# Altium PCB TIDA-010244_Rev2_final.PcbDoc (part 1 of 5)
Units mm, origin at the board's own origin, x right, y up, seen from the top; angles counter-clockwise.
Board outline 155.23 x 187.6 mm, 4 copper layers (GND/Signal 1, Solid GND Layer 1, Solid Power Layer 1, GND/Signal Layer 2), stack 1.59 mm thick; 350 components, 237 nets, 1153 pads, 380 vias.
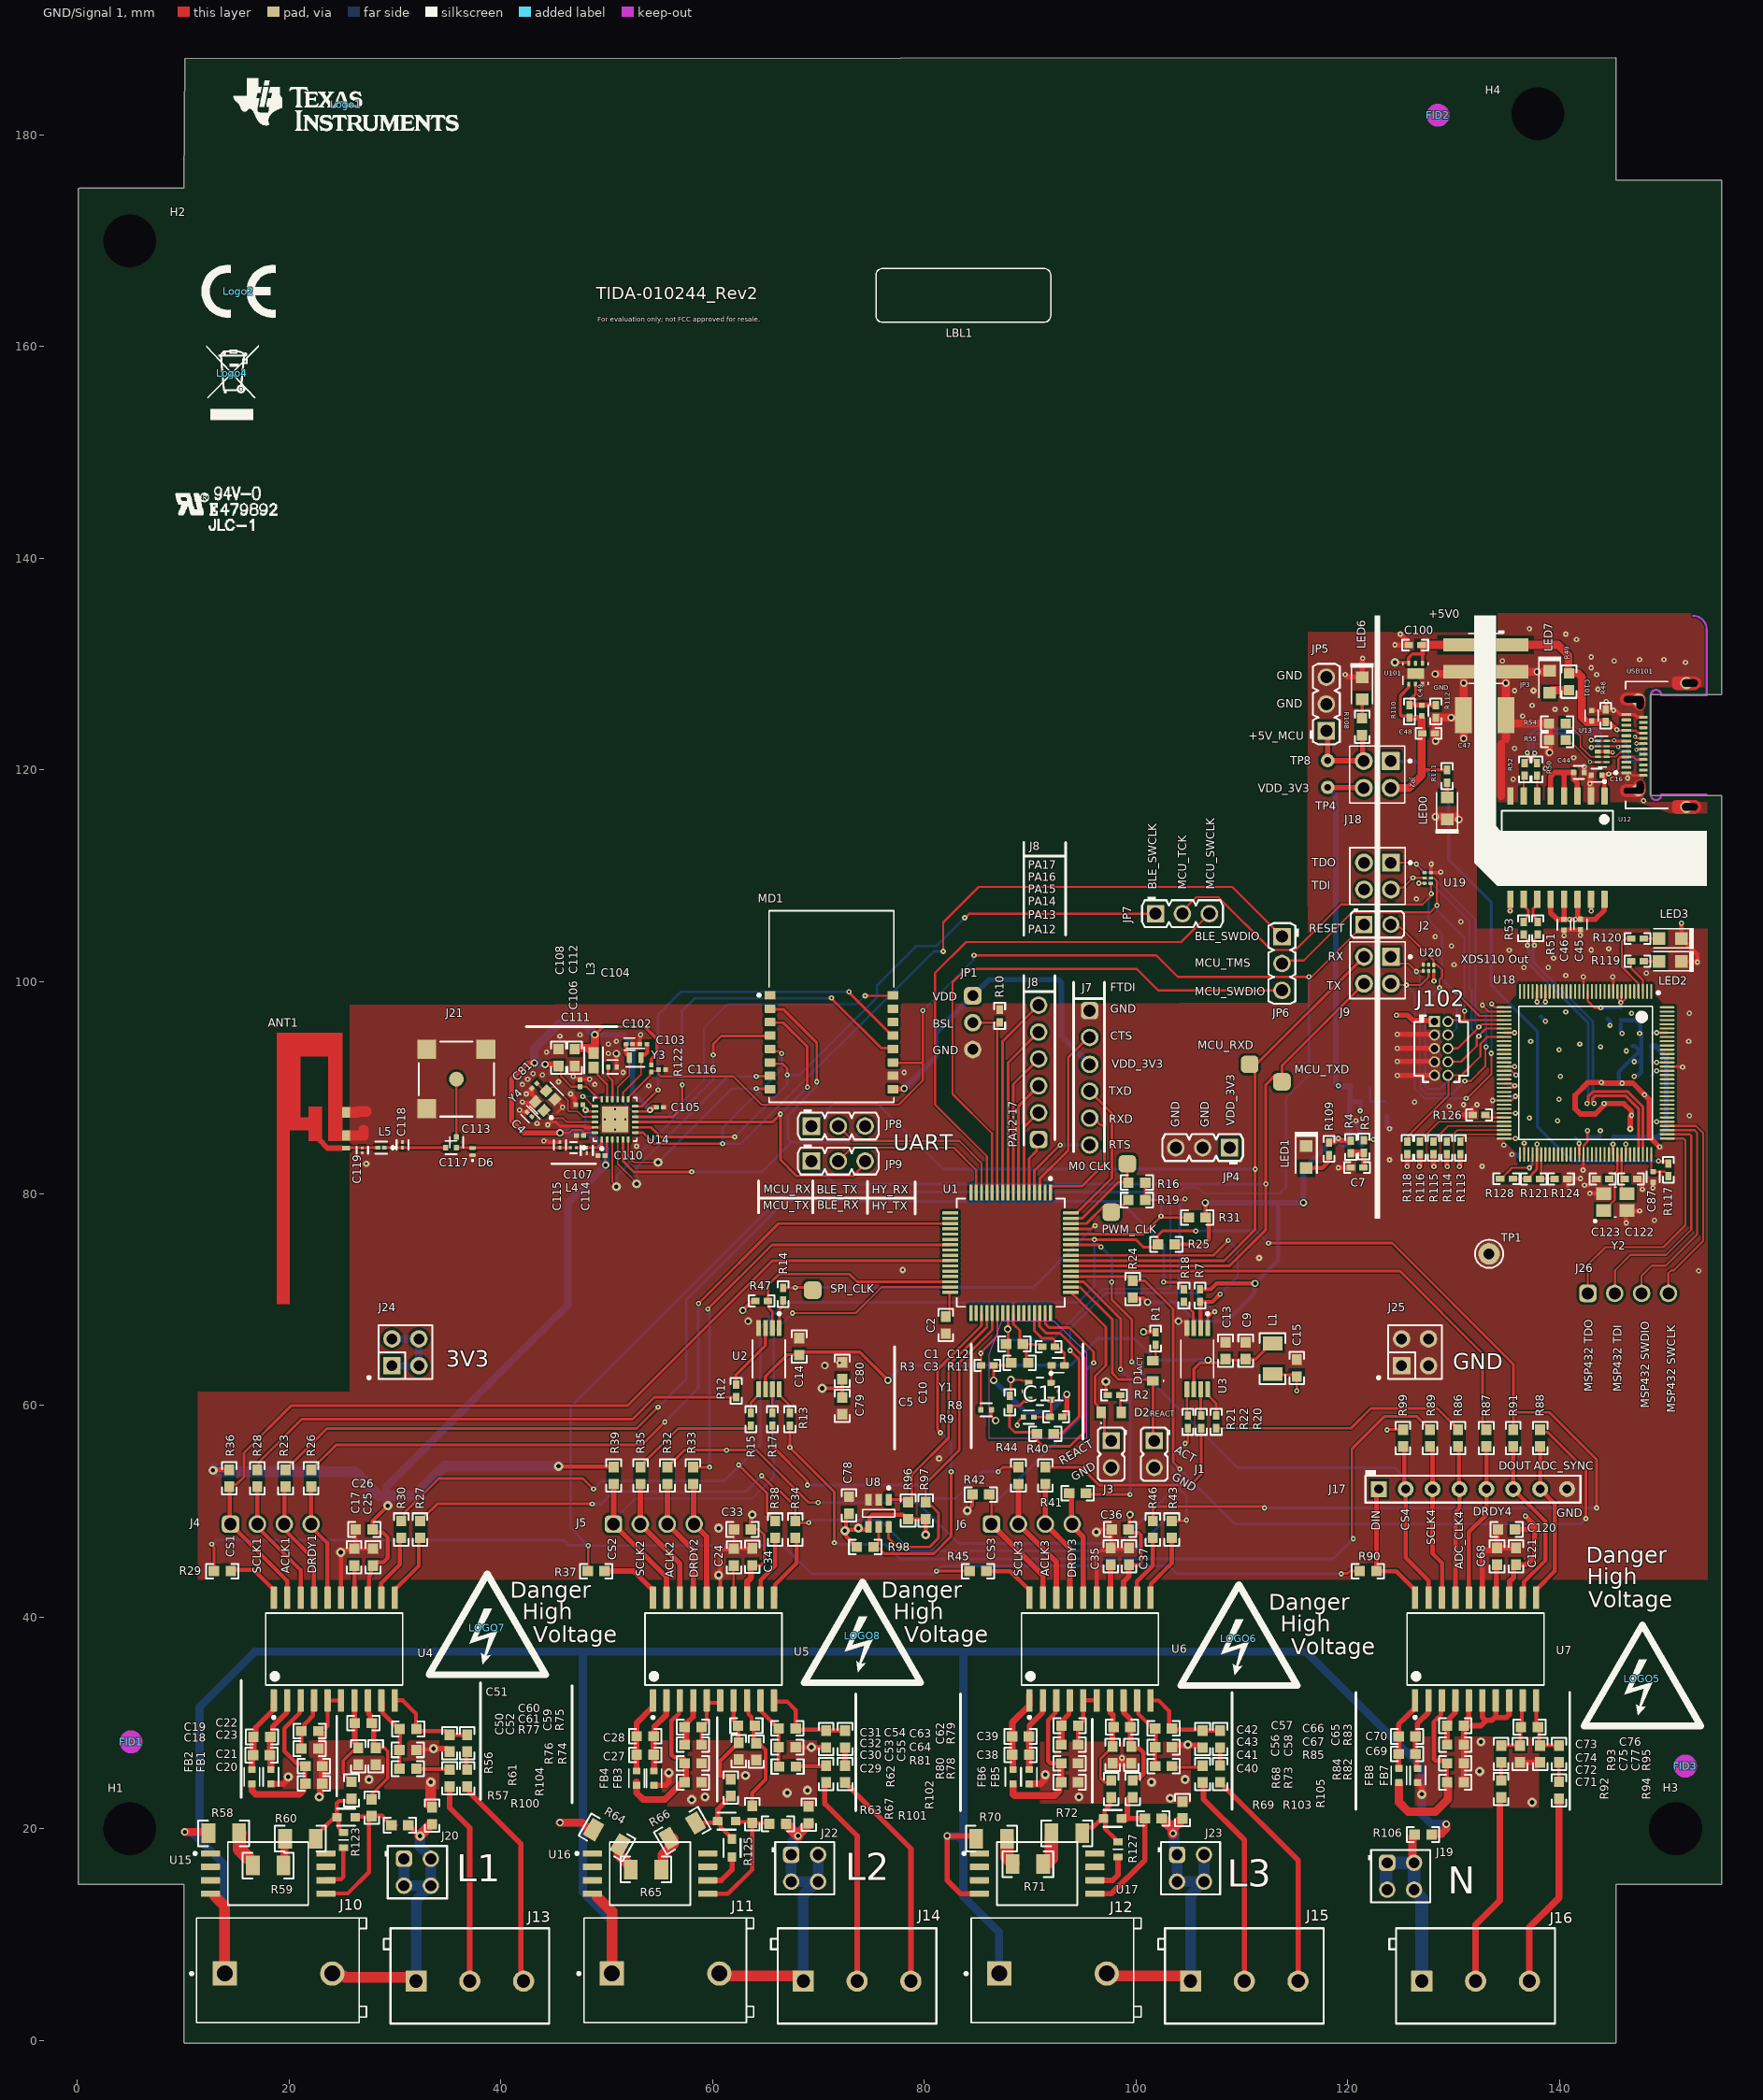
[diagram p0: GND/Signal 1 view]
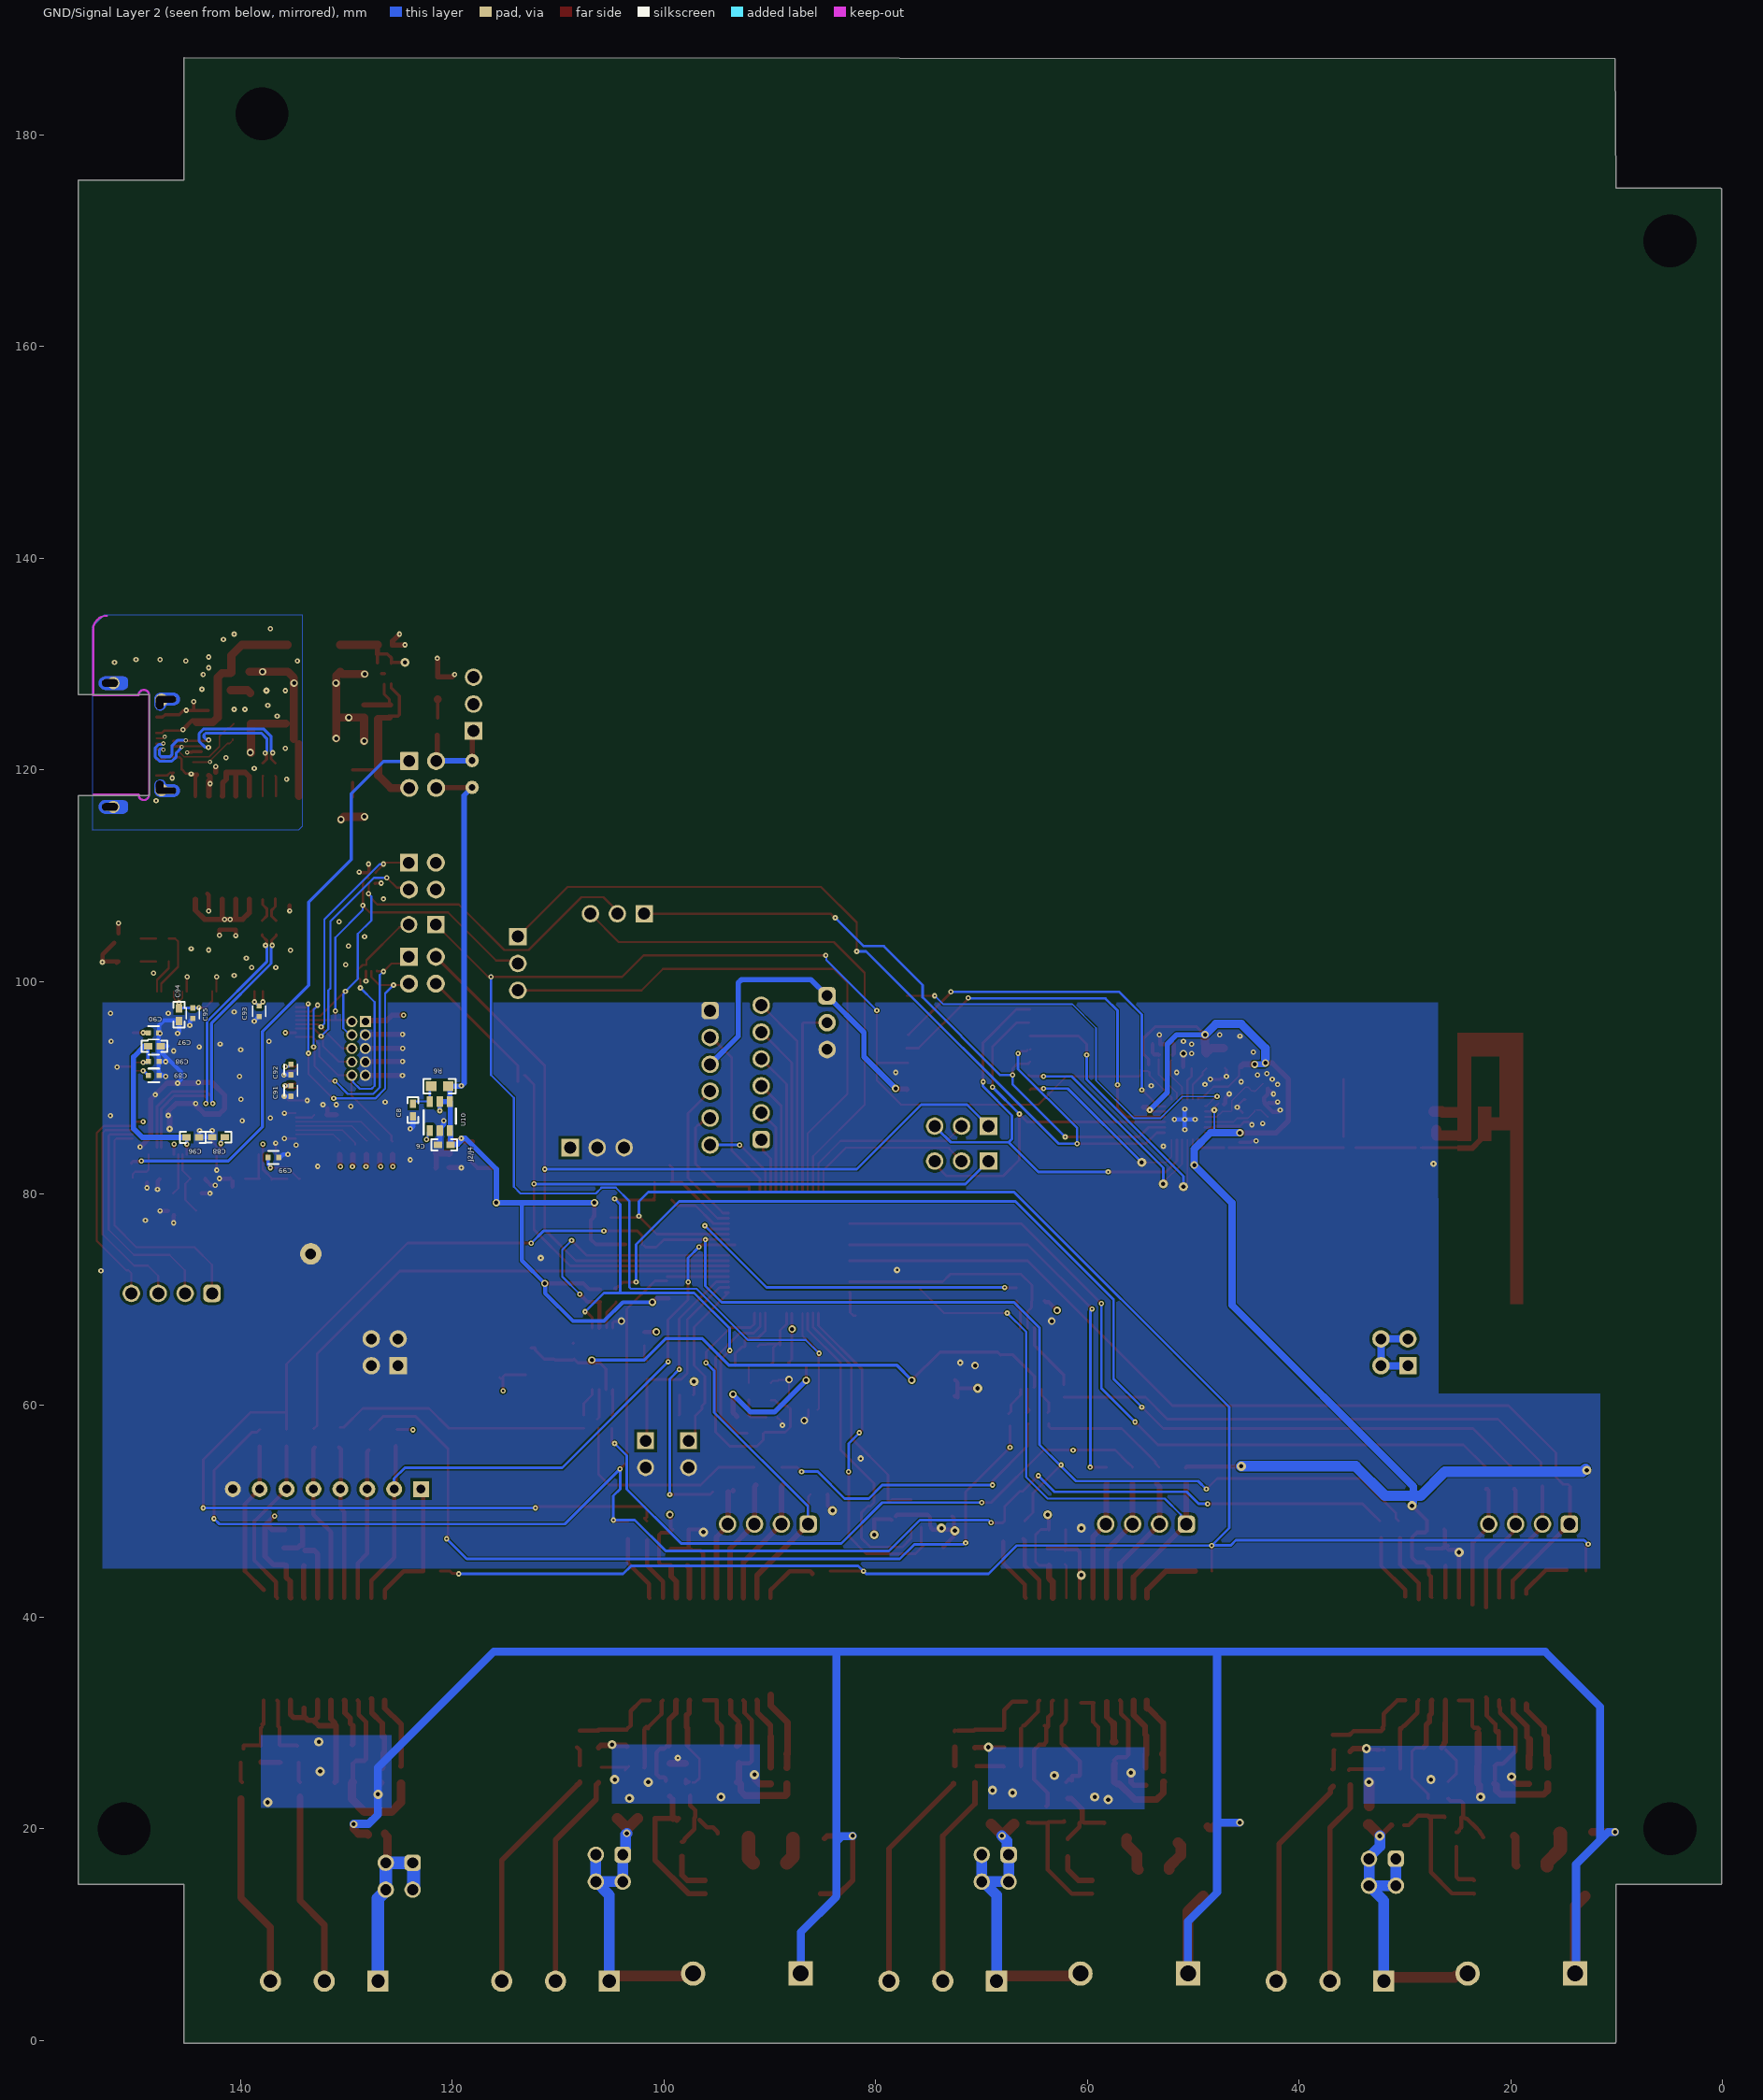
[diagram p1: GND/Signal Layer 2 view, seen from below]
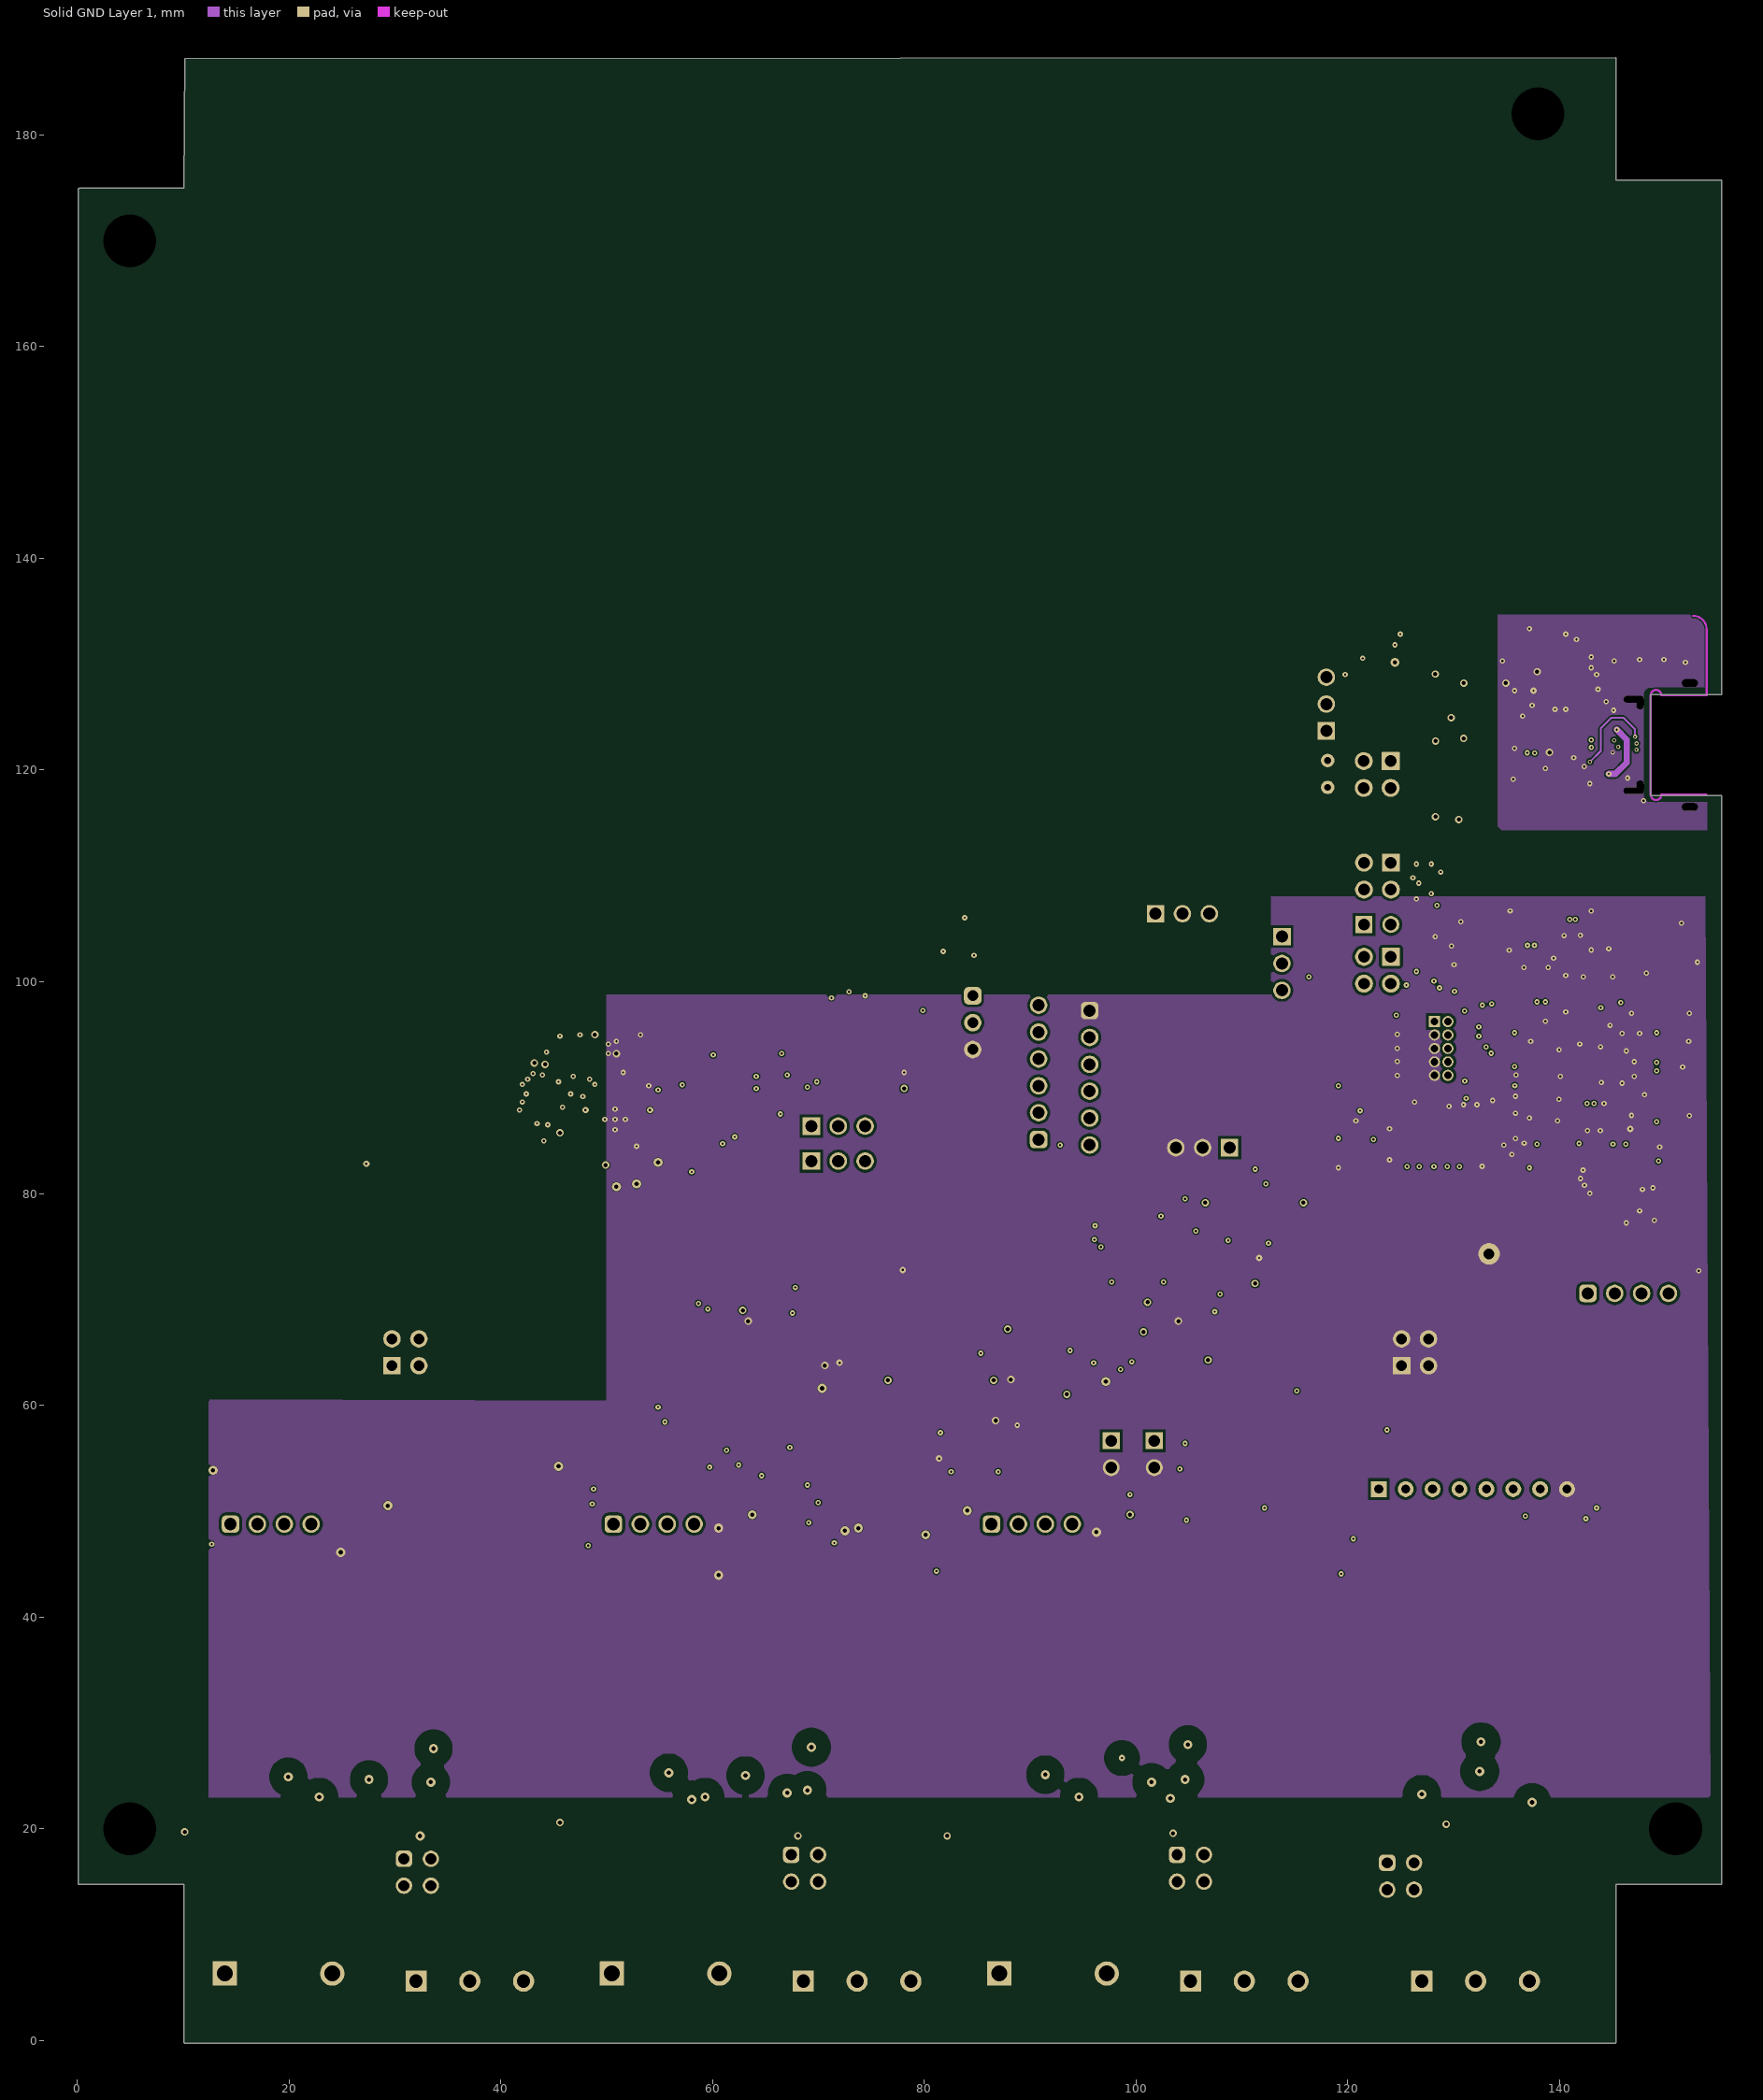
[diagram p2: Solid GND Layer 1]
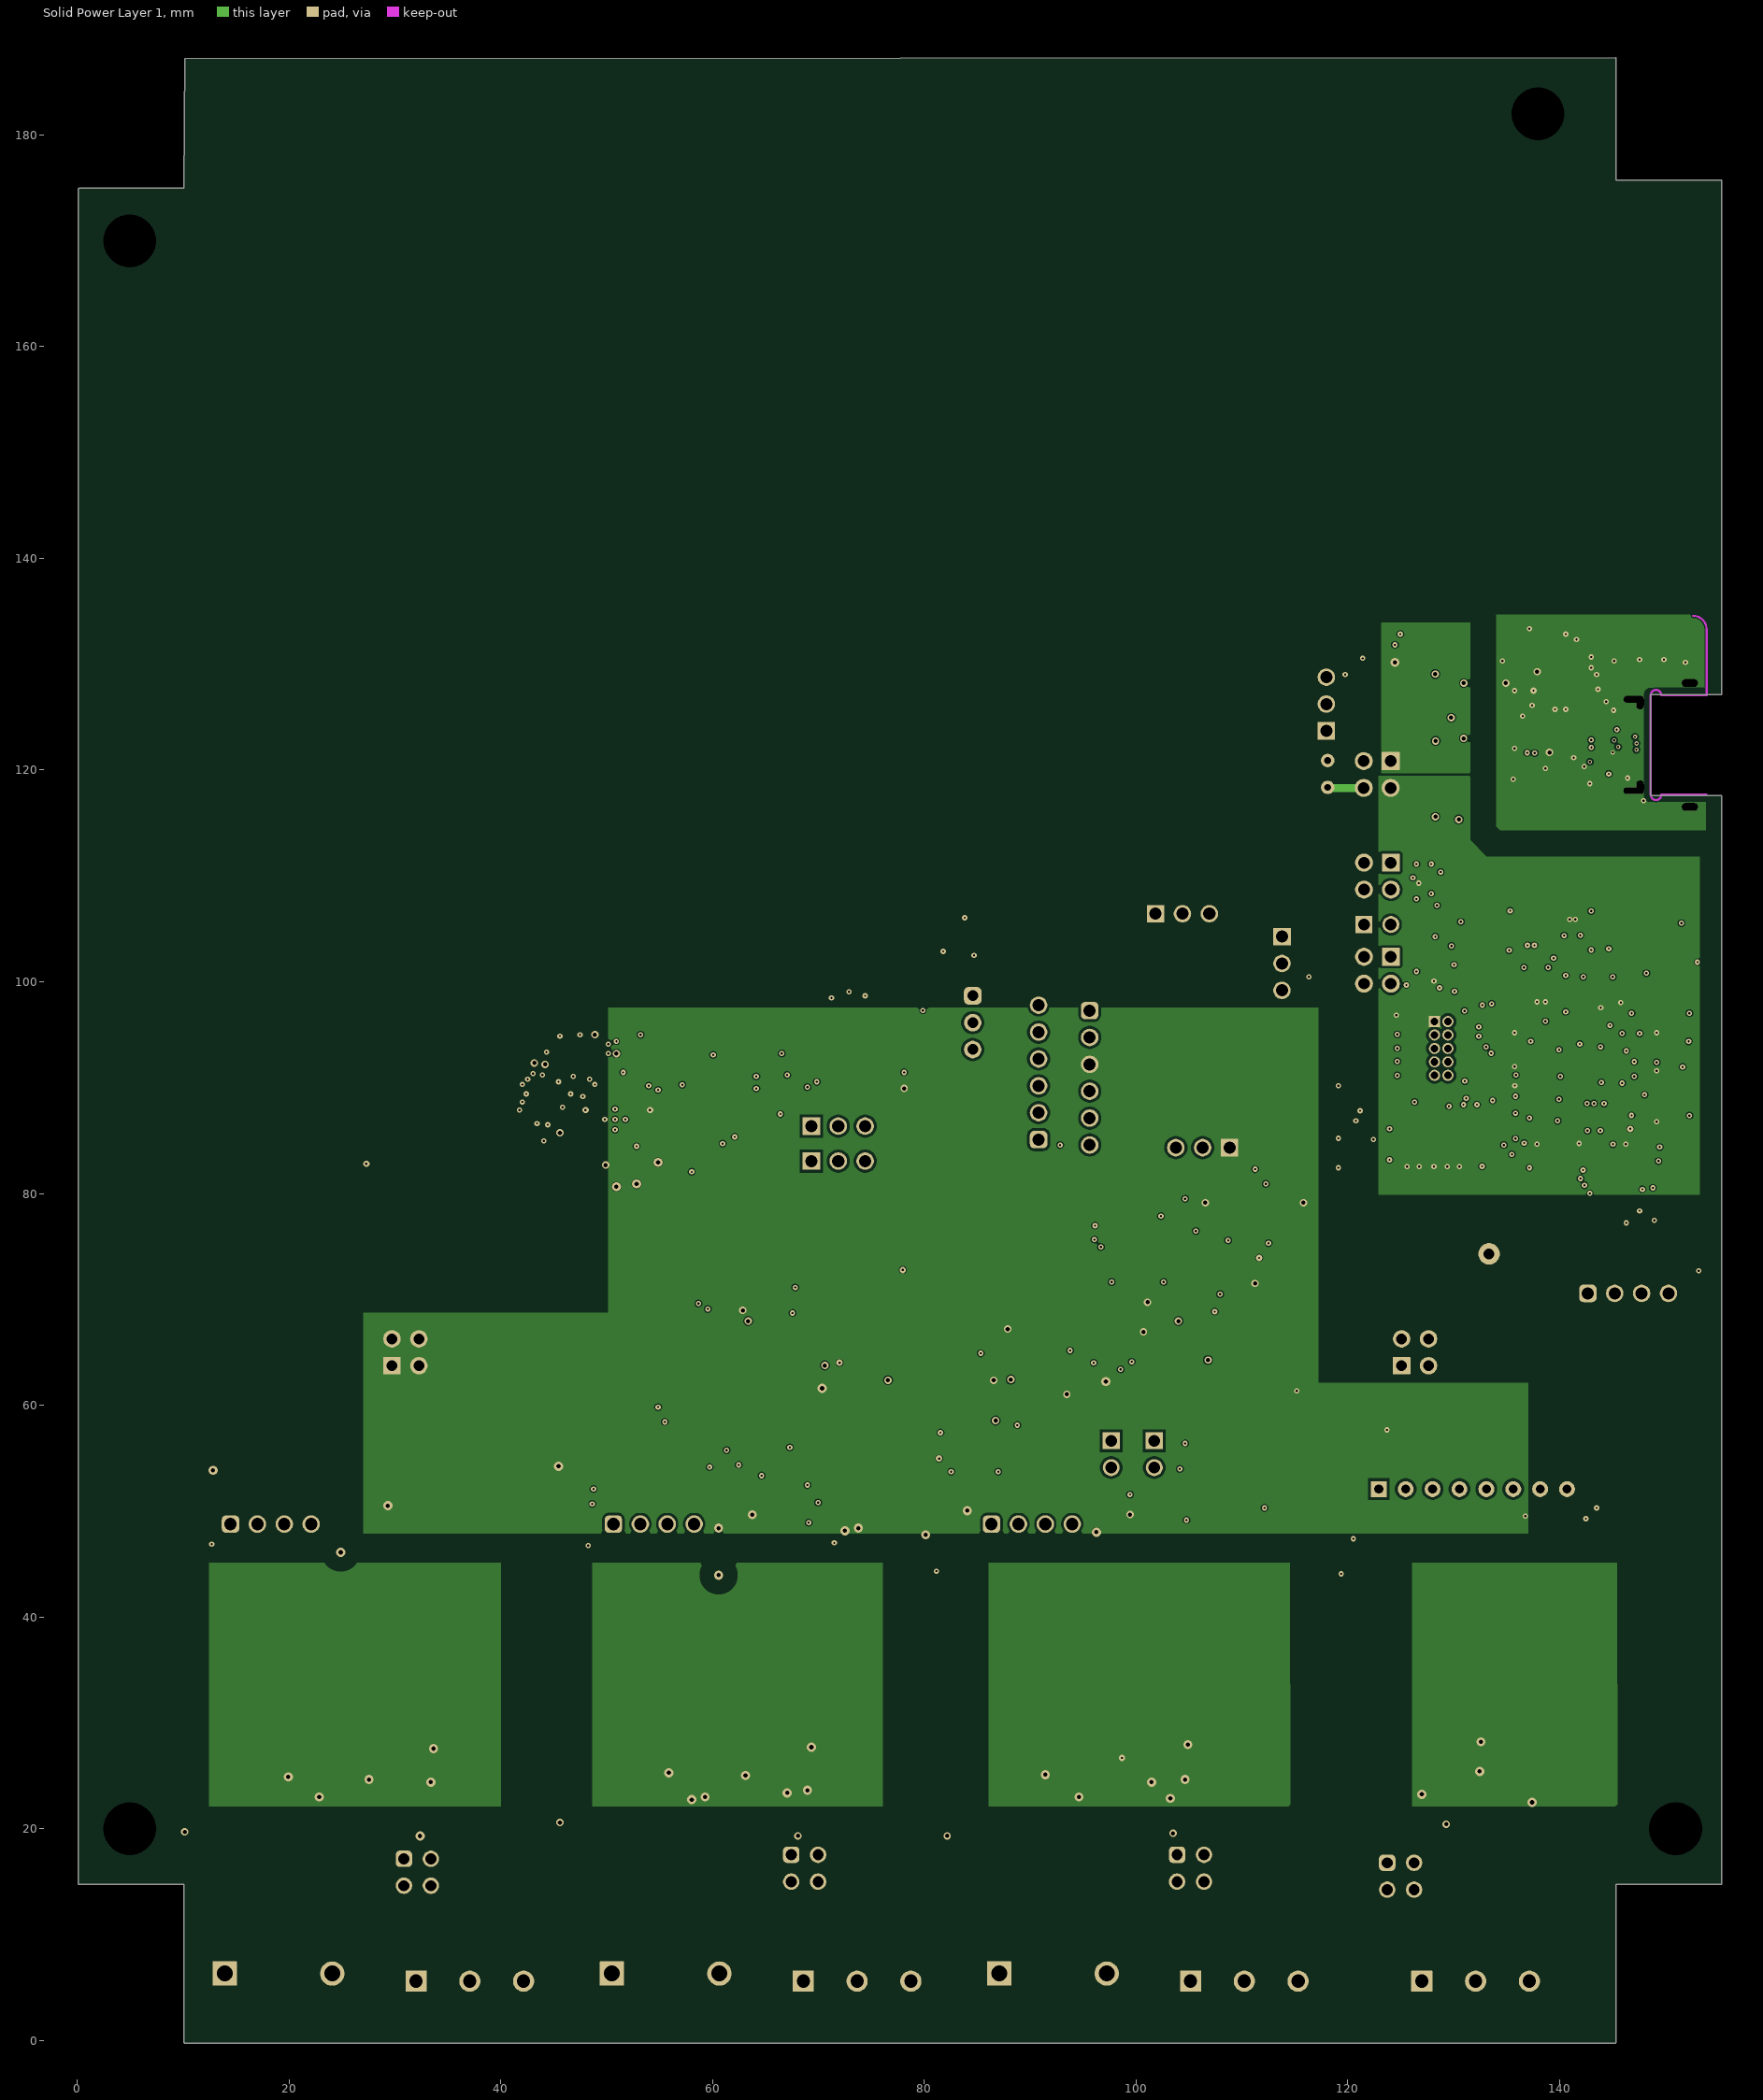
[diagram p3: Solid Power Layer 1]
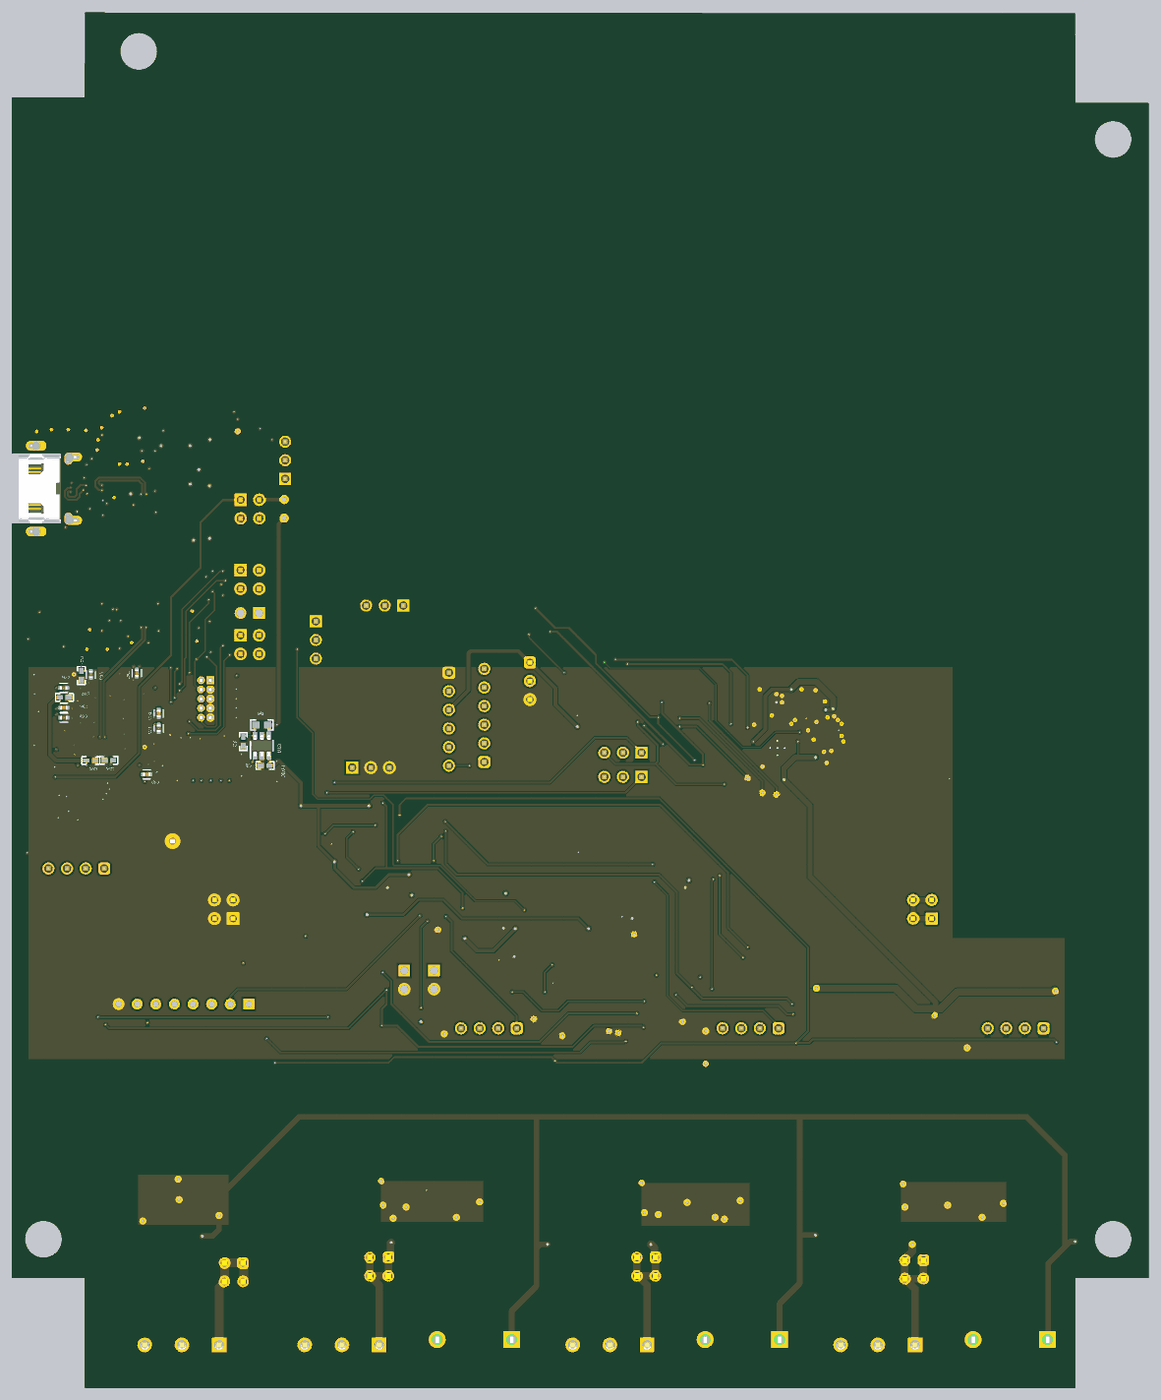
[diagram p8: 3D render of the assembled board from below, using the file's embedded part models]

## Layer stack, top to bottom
Top Solder: solder mask 0.0102, Solder Resist, Dk 3.5
GND/Signal 1: signal copper 0.0356
Dielectric 1: prepreg 0.2286, PP-006, Dk 4.1
Solid GND Layer 1: signal copper 0.0356
Dielectric1: core 0.9906, FR-4 High Tg, Dk 4.8
Solid Power Layer 1: signal copper 0.0356
Dielectric 2: prepreg 0.2286, PP-006, Dk 4.1
GND/Signal Layer 2: signal copper 0.0356
Bottom Solder: solder mask 0.0102, Solder Resist, Dk 3.5

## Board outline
10.091,-0.161 10.091,14.712 0.219,14.712 cw(c0.219,14.839) 0.091,14.839 0.091,174.839 cw(c0.219,174.839) 0.219,174.967 10.091,174.967 10.161,187.197 145.334,187.308 145.32,187.265 145.346,175.717 155.321,175.717 155.321,127.127 148.59,127.127 148.59,117.602 155.321,117.602 155.321,14.732 145.346,14.732 145.346,-0.161 cw(c145.219,-0.161) 145.219,-0.288 10.219,-0.288 cw(c10.219,-0.161)

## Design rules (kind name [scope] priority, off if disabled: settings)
AcuteAngle [All] p1: minimum=4.50000000000000E+0001 checktracksonly=FALSE
AssemblyTestPointUsage [All] p1: valid=2
BoardOutlineClearance BoardOutlineClearance_MountingHoles [OnCopper and InComponentClass('Mounting Holes')] p1: gap=1 ignorepadtopadclearanceinfootprint=FALSE
BoardOutlineClearance BoardOutlineClearance_Poly [OnCopper and IsPoly] p2: gap=0.635 ignorepadtopadclearanceinfootprint=FALSE
BoardOutlineClearance [OnCopper and Not InComponentClass('Logo') and not InComponentClass('FiducialMark') and not InRegion(1000,500,4000,800) and not InPoly] p3: gap=1.016 ignorepadtopadclearanceinfootprint=FALSE
Clearance Clearance_HGNDA_GND [InNet('GND') vs InNet('HGND_A_FB')] p1: gap=0.762 ignorepadtopadclearanceinfootprint=TRUE except(1.397: Arc-Via Track-Via SMDPad-Via THPad-Via Via-Via Via-Fill Via-Poly Via-Region Via-Text Via-Hole)
Clearance Clearance_HGNDB_GND [InNet('GND') vs InNet('HGND_B_FB')] p2: gap=0.762 ignorepadtopadclearanceinfootprint=TRUE except(1.397: Arc-Via Track-Via SMDPad-Via THPad-Via Via-Via Via-Fill Via-Poly Via-Region Via-Text Via-Hole)
Clearance Clearance_HGNDC_GND [InNet('GND') vs InNet('HGND_C_FB')] p3: gap=0.762 ignorepadtopadclearanceinfootprint=TRUE except(1.397: Arc-Via Track-Via SMDPad-Via THPad-Via Via-Via Via-Fill Via-Poly Via-Region Via-Text Via-Hole)
Clearance Clearance_HGNDD_GND [InNet('GND') vs InNet('HGND_D_FB')] p4: gap=0.762 ignorepadtopadclearanceinfootprint=TRUE except(1.397: Arc-Via Track-Via SMDPad-Via THPad-Via Via-Via Via-Fill Via-Poly Via-Region Via-Text Via-Hole)
Clearance Clearance_Keepouts [((IsTrack Or IsArc) And Not InPoly) And IsFree and IsKeepOut vs ((IsTrack Or IsArc) And Not InPoly) And IsFree and IsKeepOut] p5: gap=0.152 ignorepadtopadclearanceinfootprint=FALSE
Clearance Clearance_Poly [InPolygon] p6: gap=0.254 ignorepadtopadclearanceinfootprint=TRUE except(0: Via-Poly; 0.127: Arc-Arc Arc-Track Arc-SMDPad Arc-THPad Arc-Fill Arc-Poly Arc-Region Track-Track Track-SMDPad Track-Fill Track-Poly Track-Region SMDPad-SMDPad)
Clearance Clearance_FiducialMark [IsKeepOut and InComponentClass('FiducialMark') vs IsPad and InComponentClass('FiducialMark')] p7: gap=0 ignorepadtopadclearanceinfootprint=FALSE
Clearance [All] p8: gap=0 ignorepadtopadclearanceinfootprint=TRUE
ComponentClearance ComponentClearance_MountingHoles_FiducialMarks [InComponentClass('Mounting Holes') vs InComponentClass('FiducialMark')] p1: gap=1.27 collisioncheckmode=3 verticalgap=0.254 showdistances=TRUE
ComponentClearance ComponentClearance_Shunt [InComponentClass('Header') vs InComponentClass('Shunt')] p2: gap=0 collisioncheckmode=3 verticalgap=0 showdistances=TRUE
ComponentClearance ComponentClearance_Logo [InComponentClass('Logo')] p3: gap=0.762 collisioncheckmode=3 verticalgap=0.254 showdistances=TRUE
ComponentClearance ComponentClearance_ScrewToNut [(HasFootprint('NY PMS 440 0025 PH')) vs (HasFootprint('Keystone_1902C'))] p4: gap=0.127 collisioncheckmode=3 verticalgap=0.254 showdistances=TRUE
ComponentClearance ComponentClearance_MountingHoles [InComponentClass('Mounting Holes')] p5: gap=2.54 collisioncheckmode=3 verticalgap=25.4 showdistances=TRUE
ComponentClearance ComponentClearance_SmallPassives [HasFootprint('0201*') or HasFootprint('0402*') or HasFootprint('0508') or HasFootprint('0603*') or HasFootprint('0612') or HasFootprint('0805*') or HasFootprint('0815*') or HasFootprint('0830*') or HasFootprint('1206*') or HasFootprint('1210*') or HasFootprint('1808*') or HasFootprint('1812*') or HasFootprint('1825*') or HasFootprint('2010*') or HasFootprint('2220*') or HasFootprint('2225*') or HasFootprint('2512*') or HasFootprint('2728*') or HasFootprint('3518*') vs HasFootprint('0201*') or HasFootprint('0402*') or HasFootprint('0508') or HasFootprint('0603*') or HasFootprint('0612') or HasFootprint('0805*') or HasFootprint('0815*') or HasFootprint('0830*') or HasFootprint('1206*') or HasFootprint('1210*') or HasFootprint('1808*') or HasFootprint('1812*') or HasFootprint('1825*') or HasFootprint('2010*') or HasFootprint('2220*') or HasFootprint('2225*') or HasFootprint('2512*') or HasFootprint('2728*') or HasFootprint('3518*')] p6: gap=0.38 collisioncheckmode=3 verticalgap=0.254 showdistances=TRUE
ComponentClearance ComponentClearance_THtoSMT [IsThruComponent vs IsSMTComponent] p7: gap=0.762 collisioncheckmode=3 verticalgap=0.762 showdistances=TRUE
ComponentClearance ComponentClearance_THtoTH [IsThruComponent vs IsThruComponent] p8: gap=0.508 collisioncheckmode=3 verticalgap=0.254 showdistances=TRUE
ComponentClearance [All] p9: gap=0.508 collisioncheckmode=3 verticalgap=0 showdistances=TRUE
DiffPairsRouting [All] p1: maxlimit=2.54 minlimit=0.254 mostfreqgap=0.254 toplayer_minwidth=0.381 toplayer_maxwidth=0.381 toplayer_prefwidth=0.381 midlayer1_minwidth=0.381 midlayer1_maxwidth=0.381 midlayer1_prefwidth=0.381 midlayer2_minwidth=0.381 midlayer2_maxwidth=0.381 midlayer2_prefwidth=0.381 bottomlayer_minwidth=0.381 bottomlayer_maxwidth=0.381 bottomlayer_prefwidth=0.381 maxuncoupledlength=25.4
FabricationTestPointUsage TestPointUsage [All] p1: valid=2 allowmultiple=FALSE
FabricationTestpoint Testpoint [All] p1: side=3 testpointundercomponent=TRUE minsize=1.016 maxsize=2.54 preferedsize=1.524 minholesize=0 maxholesize=1.016 preferedholesize=0.813 testpointgrid=0.025 allowsidetop=TRUE allowsidebottom=TRUE usegrid=TRUE gridtolerance=0
FanoutControl Fanout_LCC [IsLCC] p1: bgadir=Out bgaviamode=Centered fanoutstyle=Auto fanoutdirection=Alternating viagrid=0.025 // Fanout_LCC (Default Rule)
FanoutControl Fanout_BGA [IsBGA] p2: bgadir=Out bgaviamode=Centered fanoutstyle=Auto fanoutdirection=Alternating viagrid=0.025 // Fanout_BGA (Default Rule)
HoleSize [All] p1: absolutevalues=TRUE maxlimit=6.375 minlimit=0.2 maxpercent=80.000 minpercent=20.000
MatchedLengths SPI_Buffer_To_ADC_Matched_2 [InNetClass('SPI_CLK_Group_2')] p1: tolerance=0.645 checknetsindiffpair=FALSE checkdiffpairvsdiffpair=TRUE checkxsignals=TRUE checkothers=TRUE targetsourcename="Not defined"
MatchedLengths SPI_To_Buffer_Matched [InNetClass('Phase1_SPI_To_Header')] p2: tolerance=0.645 checknetsindiffpair=FALSE checkdiffpairvsdiffpair=TRUE checkxsignals=TRUE checkothers=TRUE targetsourcename="Not defined"
MinimumAnnularRing MinimumAnnularRing_ThermalPadVias [IsVia and InAnyComponent] p1: minimumring=0.127
MinimumAnnularRing [All] p2: minimumring=0.127
MinimumSolderMaskSliver MinimumSolderMaskSliver_Logo [InComponentClass('Logo') vs InComponentClass('Logo')] p1: minsoldermaskwidth=0.018
MinimumSolderMaskSliver [All] p2: minsoldermaskwidth=0.1
PlaneConnect [All] p1: planeconnectstyle=Relief reliefexpansion=0.254 reliefentries=4 reliefconductorwidth=0.254 reliefairgap=0.254
PolygonConnect [All] p1: connectstyle=Direct reliefconductorwidth=0.254 reliefentries=4 polygonreliefangle="90 Angle" airgapwidth=0.254
RoutingLayers [All] p1: top layer_v5=TRUE mid layer 1_v5=FALSE mid layer 2_v5=FALSE bottom layer_v5=TRUE
RoutingVias RoutingVias_1 [All] p1: holewidth=0.406 width=0.864 viastyle="Through Hole" minholewidth=0.2 minwidth=0.2 maxholewidth=1.016 maxwidth=1.651
RoutingVias ThermalPadVias [IsVia and InAnyComponent] p2: holewidth=0.2 width=0.5 viastyle="Through Hole" minholewidth=0.2 minwidth=0.5 maxholewidth=0.33 maxwidth=0.6
RoutingVias [All] p3: holewidth=0.406 width=0.864 viastyle="Through Hole" minholewidth=0.2 minwidth=0.61 maxholewidth=1.016 maxwidth=1.651
SilkToSilkClearance SilkToSilkClearance_Pb-FreeLogo [(HasFootprint('Pb-Free_Overlay_Medium') OR HasFootprint('Pb-Free_Overlay_Small')) vs (HasFootprint('Pb-Free_Overlay_Medium') OR HasFootprint('Pb-Free_Overlay_Small'))] p1: silktosilkclearance=0
SilkToSilkClearance [All] p2: silktosilkclearance=0.1
SilkToSolderMaskClearance SilkToComponentPadClearance [(IsPad or IsFill or IsRegion) and InAnycomponent] p1: minsilkscreentomaskgap=0.1 clearancetoexposedcopper=TRUE
SilkToSolderMaskClearance "Silk to Solder Mask Opening" [All] p2: minsilkscreentomaskgap=0.1 clearancetoexposedcopper=FALSE
SolderMaskExpansion [All] p1: expansion=0.05 istentingtop=FALSE
SupplyNets "Schematic Supply Nets_7" [InNet('HGND_B_FB')] p1: voltage=0.000
SupplyNets "Schematic Supply Nets_6" [InNet('HGND_C_FB')] p2: voltage=0.000
SupplyNets "Schematic Supply Nets_27" [InNet('HGND_A_FB')] p3: voltage=0.000
SupplyNets "Schematic Supply Nets_26" [InNet('HGND_D_FB')] p4: voltage=0.000
SupplyNets "Schematic Supply Nets_28" [InNet('+5V0_MCU')] p5: voltage=0.000
SupplyNets "Schematic Supply Nets_25" [InNet('+3V3_XDS110')] p6: voltage=0.000
SupplyNets "Schematic Supply Nets_24" [InNet('+5V0_XDS110')] p7: voltage=0.000
SupplyNets "Schematic Supply Nets_23" [InNet('+5V0_USB')] p8: voltage=0.000
SupplyNets "Schematic Supply Nets_22" [InNet('DCDC_HGND_D')] p9: voltage=0.000
SupplyNets "Schematic Supply Nets_21" [InNet('GND')] p10: voltage=0.000
SupplyNets "Schematic Supply Nets_20" [InNet('HLDO_OUT_C')] p11: voltage=0.000
SupplyNets "Schematic Supply Nets_19" [InNet('HLDO_OUT_A')] p12: voltage=0.000
SupplyNets "Schematic Supply Nets_18" [InNet('DCDC_HGND_C')] p13: voltage=0.000
SupplyNets "Schematic Supply Nets_17" [InNet('DCDC_HGND_A')] p14: voltage=0.000
SupplyNets "Schematic Supply Nets_16" [InNet('VDD_3V3')] p15: voltage=0.000
SupplyNets "Schematic Supply Nets_15" [InNet('DCDC_OUT_D')] p16: voltage=0.000
SupplyNets "Schematic Supply Nets_14" [InNet('DCDC_OUT_B')] p17: voltage=0.000
SupplyNets "Schematic Supply Nets_12" [InNet('HLDO_OUT_B')] p18: voltage=0.000
SupplyNets "Schematic Supply Nets_11" [InNet('HLDO_IN_C')] p19: voltage=0.000
SupplyNets "Schematic Supply Nets_10" [InNet('HLDO_OUT_D')] p20: voltage=0.000
SupplyNets "Schematic Supply Nets_9" [InNet('DCDC_OUT_C')] p21: voltage=0.000
SupplyNets "Schematic Supply Nets_8" [InNet('HLDO_IN_A')] p22: voltage=0.000
SupplyNets "Schematic Supply Nets_5" [InNet('DCDC_HGND_B')] p23: voltage=0.000
SupplyNets "Schematic Supply Nets_4" [InNet('USB_GND')] p24: voltage=0.000
SupplyNets "Schematic Supply Nets_3" [InNet('DCDC_OUT_A')] p25: voltage=0.000
SupplyNets "Schematic Supply Nets_2" [InNet('HLDO_IN_D')] p26: voltage=0.000
SupplyNets "Schematic Supply Nets_1" [InNet('HLDO_IN_B')] p27: voltage=0.000
UnRoutedNet [All] p1: checkbadconnections=TRUE
Width [All] p1: maxlimit=1.8 minlimit=0.12 preferedwidth=0.229 minimp=50.000000 maximp=50.000000 favimp=50.000000
16 further rules are at their usual default settings.

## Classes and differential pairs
component class TIDA-010244_BLE_Module_HY-2340: MD1
component class TIDA-010244_XDS110_MCU: C87 C88 C89 C90 C91 C92 C93 C94 C95 C96 C97 C98 C99 C122 C123 J9 J18 J26 J102 LED2 LED3 R113 R114 R115 R116 R117 R118 R119 R120 R121 R124 R126 R128 U18 U19 U20 Y2
component class TIDA-010244_USB_and_Power: C6 C7 C8 C16 C44 C45 C46 C47 C48 C49 C100 C101 JP2 JP3 JP4 JP5 LED0 LED1 LED6 LED7 q R4 R5 R6 R48 R49 R50 R51 R52 R53 R54 R55 R108 R109 R110 R111 R112 TP4 TP8 U10 U12 U13 U101 USB101
component class TIDA-010244_Neutral_3DHall_Rev2: C68 C69 C70 C71 C72 C73 C74 C75 C76 C77 C78 C120 C121 FB7 FB8 J16 J17 J19 R86 R87 R88 R89 R90 R91 R92 R93 R94 R95 R96 R97 R98 R99 R106 U7 U8
component class TIDA-010244_BLE_Wireless: ANT1 C4 C81 C102 C103 C104 C105 C106 C107 C108 C110 C111 C112 C113 C114 C115 C116 C117 C118 C119 D6 J21 JP6 JP7 JP8 JP9 L3 L4 L5 R122 U14 Y3 Y4
component class TIDA-010244_MSPM0G_Rev2: C1 C2 C3 C5 C9 C10 C11 C12 C13 C14 C15 C79 C80 D1 D2 J1 J2 J3 J7 J8 JP1 L1 R1 R2 R3 R7 R8 R9 R10 R11 R12 R13 R14 R15 R16 R17 R18 R19 R20 R21 R22 R47 TP1 U1 U2 U3 Y1
component class Header: J1 J2 J3 J4 J5 J6 J7 J8 J17 J24 J25 J26 JP1 JP3 JP4 JP5 JP6 JP7 JP8 JP9
component class TIDA-010244_V_I_Filtering_FE_Rev2: C50 C51 C52 C53 C54 C55 C56 C57 C58 C59 C60 C61 C62 C63 C64 C65 C66 C67 J10 J11 J12 J13 J14 J15 J20 J22 J23 J24 J25 R56 R57 R58 R59 R60 R61 R62 R63 R64 R65 R66 R67 R68 R69 R70 R71 R72 R73 R74 R75 R76 R77 R78 R79 R80 R81 R82 R83 R84 R85 R100 R101 R102 R103 R104 R105 R123 R125 R127 U15 U16 U17
component class TIDA-010244_3xISO_ADC_Rev2: C17 C18 C19 C20 C21 C22 C23 C24 C25 C26 C27 C28 C29 C30 C31 C32 C33 C34 C35 C36 C37 C38 C39 C40 C41 C42 C43 FB1 FB2 FB3 FB4 FB5 FB6 J4 J5 J6 R23 R24 R25 R26 R27 R28 R29 R30 R31 R32 R33 R34 R35 R36 R37 R38 R39 R40 R41 R42 R43 R44 R45 R46 U4 U5 U6
component class Logo: Logo1
component class TIDA-010244_Hardware: FID1 FID2 FID3 H1 H2 H3 H4 LBL1 Logo1 Logo2 Logo3 Logo4 LOGO5 LOGO6 LOGO7 LOGO8 ZZ1 ZZ2 ZZ3 ZZ4
component class FiducialMark: FID1 FID2 FID3
component class AssemblyNote: ZZ1 ZZ2 ZZ3 ZZ4
component class Label: LBL1

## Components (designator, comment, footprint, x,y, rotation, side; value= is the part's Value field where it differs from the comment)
ANT1 "Inverted F Antenna" 0-MFG 22.315,82.361 r270 top locked
C1 "C0603C105K3RACTU" 0603 88.519,65.786 r0 top value=1uF
C2 "GRM188R61A474KA61D" 0603 82.042,67.564 r90 top value=0.47uF
C3 "GRM188R61A106KAALD" 0603 89.027,64.008 r180 top value=10uF
C4 "GRM0335C1H150GA01D" FP-GRM0335C1H150GA01D_0201-IPC_B 42.711,87.464 r315 top value=15pF
C5 "885012205050" FP-885012205050_0402-MFG 85.852,59.563 r180 top value=10nF
C6 "GRM155R71A104KA01D" 0402 120.742,84.595 r180 bottom value=0.1uF
C7 "GRM155R71E103KA01D" 0402 120.879,82.455 r180 top value=0.01uF
C8 "GRM155R71E103KA01D" 0402 123.698,87.884 r270 bottom value=0.01uF
C9 "CGA3E1X7R1C105K080AC" 0603 110.363,65.151 r90 top value=1uF
C10 "GRM1555C1H150JA01D" 0402 88.076,60.272 r90 top value=15pF
C11 "885012205018" FP-885012205018_0402-MFG 89.856,58.866 r0 top value=100nF
C12 "GRM1555C1H150JA01D" 0402 91.752,65.527 r0 top value=15pF
C13 "C1608X7R1H104K080AA" 0603 108.458,65.151 r270 top value=0.1uF
C14 "C1608X7R1H104K080AA" 0603 68.199,65.532 r270 top value=0.1uF
C15 "GRM188R61A106KAALD" 0603 115.189,63.5 r90 top value=10uF
C16 "885012205018" FP-885012205018_0402-MFG 143.51,119.507 r0 top value=100nF
C17 "C1608X7R1H104K080AA" 0603 26.162,45.644 r90 top value=0.1uF
C18 "C0603C105K3RACTU" 0603 17.406,26.946 r180 top value=1uF
C19 "C0603C102K5RACTU" 0603 17.432,28.663 r0 top value=1000pF
C20 "C1608X7R1H104K080AA" 0603 22.352,24.257 r0 top value=0.1uF
C21 "C0603C102K5RACTU" 0603 22.352,25.908 r0 top value=1000pF
C22 "C0603C102K5RACTU" 0603 21.971,29.21 r0 top value=1000pF
C23 "C1608X7R1H104K080AA" 0603 21.971,27.559 r0 top value=0.1uF
C24 "C1608X7R1H104K080AA" 0603 62.027,45.644 r90 top value=0.1uF
C25 "C0603C105K3RACTU" 0603 27.94,45.644 r270 top value=1uF
C26 "C0603C102K5RACTU" 0603 27.102,48.26 r180 top value=1000pF
C27 "C0603C105K3RACTU" 0603 53.631,26.975 r180 top value=1uF
C28 "C0603C102K5RACTU" 0603 53.631,28.727 r0 top value=1000pF
C29 "C1608X7R1H104K080AA" 0603 58.166,24.384 r0 top value=0.1uF
C30 "C0603C102K5RACTU" 0603 58.166,26.162 r0 top value=1000pF
C31 "C0603C102K5RACTU" 0603 58.166,29.591 r0 top value=1000pF
C32 "C1608X7R1H104K080AA" 0603 58.166,27.94 r0 top value=0.1uF
C33 "C0603C105K3RACTU" 0603 62.84,48.26 r0 top value=1uF
C34 "C0603C102K5RACTU" 0603 63.754,45.669 r90 top value=1000pF
C35 "C1608X7R1H104K080AA" 0603 97.612,45.72 r90 top locked value=0.1uF
C36 "C0603C105K3RACTU" 0603 98.501,48.26 r0 top locked value=1uF
C37 "C0603C102K5RACTU" 0603 99.339,45.72 r90 top locked value=1000pF
C38 "C0603C105K3RACTU" 0603 89.114,26.975 r180 top value=1uF
C39 "C0603C102K5RACTU" 0603 89.103,28.702 r0 top value=1000pF
C40 "C1608X7R1H104K080AA" 0603 93.726,24.384 r0 top value=0.1uF
C41 "C0603C102K5RACTU" 0603 93.726,26.162 r0 top value=1000pF
C42 "C0603C102K5RACTU" 0603 93.755,29.718 r0 top value=1000pF
C43 "C1608X7R1H104K080AA" 0603 93.726,27.94 r0 top value=0.1uF
C44 "885012205018" FP-885012205018_0402-MFG 141.842,119.775 r180 top value=100nF
C45 "885012205018" FP-885012205018_0402-MFG 141.986,105.41 r90 top value=100nF
C46 "885012205018" FP-885012205018_0402-MFG 140.421,105.384 r90 top value=100nF
C47 "1812SC103KAT1A" 1812 132.944,125.171 r0 top value=0.01uF
C48 "885012105012" 0402 127.645,123.459 r0 top value=1uF
C49 "885012205050" FP-885012205050_0402-MFG 126.999,125.611 r270 top value=10nF
C50 "885012006057" 0603 26.543,26.835 r270 top value=100pF
C51 "C0603C472J1GAC7867" 0603 27.013,29.972 r0 top value=4700pF
C52 "885012006057" 0603 28.194,26.835 r90 top value=100pF
C53 "885012006057" 0603 62.484,27.305 r270 top value=100pF
C54 "C0603C472J1GAC7867" 0603 63.208,29.718 r0 top value=4700pF
C55 "885012006057" 0603 64.135,27.267 r90 top value=100pF
C56 "885012006057" 0603 97.79,26.962 r270 top value=100pF
C57 "C0603C472J1GAC7867" 0603 98.679,29.591 r0 top value=4700pF
C58 "885012006057" 0603 99.568,26.962 r90 top value=100pF
C59 "885012006057" 0603 35.179,28.067 r270 top value=100pF
C60 "C0603C472J1GAC7867" 0603 31.248,29.406 r180 top value=4700pF
C61 "885012006057" 0603 31.242,27.432 r180 top value=100pF
C62 "885012006057" 0603 70.739,28.448 r270 top value=100pF
C63 "C0603C472J1GAC7867" 0603 67.056,29.464 r180 top value=4700pF
C64 "885012006057" 0603 67.056,27.686 r180 top value=100pF
C65 "885012006057" 0603 106.299,28.448 r270 top value=100pF
C66 "C0603C472J1GAC7867" 0603 102.616,29.464 r180 top value=4700pF
C67 "885012006057" 0603 102.616,27.686 r180 top value=100pF
C68 "C1608X7R1H104K080AA" 0603 134.112,45.72 r90 top value=0.1uF
C69 "C0603C105K3RACTU" 0603 125.603,27.051 r180 top value=1uF
C70 "C0603C102K5RACTU" 0603 125.603,28.702 r0 top value=1000pF
C71 "C1608X7R1H104K080AA" 0603 130.175,24.384 r0 top value=0.1uF
C72 "C0603C102K5RACTU" 0603 130.175,26.162 r0 top value=1000pF
C73 "C0603C102K5RACTU" 0603 130.175,29.718 r0 top value=1000pF
C74 "C1608X7R1H104K080AA" 0603 130.175,27.94 r0 top value=0.1uF
C75 "885012006057" 0603 136.271,27.051 r270 top value=100pF
C76 "C0603C472J1GAC7867" 0603 137.16,29.591 r0 top value=4700pF
C77 "885012006057" 0603 138.176,27.051 r90 top value=100pF
C78 "C0603X104K3RACTU" 0603 72.898,50.546 r90 top value=0.1uF
C79 "C0603C105K3RACTU" 0603 72.263,59.944 r90 top value=1uF
C80 "C0603X104K3RACTU" 0603 72.263,63.246 r90 top value=0.1uF
C81 "GRM0335C1H120JA01D" 0201 43.18,90.17 r225 top value=12pF
C87 "885012205050" FP-885012205050_0402-MFG 148.85,81.562 r90 top value=10nF
C88 "885012105012" 0402 142.066,85.313 r0 bottom value=1uF
C89 "885012205050" FP-885012205050_0402-MFG 148.184,91.135 r0 bottom value=10nF
C90 "885012205050" FP-885012205050_0402-MFG 148.207,95.179 r0 bottom value=10nF
C91 "885012205050" FP-885012205050_0402-MFG 135.237,89.68 r90 bottom value=10nF
C92 "885012205018" FP-885012205018_0402-MFG 135.237,91.71 r90 bottom value=100nF
C93 "885012205018" FP-885012205018_0402-MFG 138.23,97.22 r90 bottom value=100nF
C94 "885012105012" 0402 145.807,96.876 r270 bottom value=1uF
C95 "885012205050" FP-885012205050_0402-MFG 144.501,97.028 r90 bottom value=10nF
C96 "885012105012" 0402 144.508,85.292 r180 bottom value=1uF
C97 "885012105012" 0402 148.118,93.908 r180 bottom value=1uF
C98 "885012205018" FP-885012205018_0402-MFG 148.182,92.485 r0 bottom value=100nF
C99 "885012205018" FP-885012205018_0402-MFG 136.882,83.4 r0 bottom value=100nF
C100 "885012105012" 0402 126.375,131.807 r180 top value=1uF
C101 "885012205064" FP-885012205064_0402-MFG 143.048,125.138 r270 top value=3.3nF
C102 "GRM0335C1H150GA01D" FP-GRM0335C1H150GA01D_0201-IPC_B 52.147,94.107 r180 top value=15pF
C103 "GRM0335C1H120JA01D" 0201 53.467,94.107 r180 top value=12pF
C104 "GRM155Z71A105KE01D" FP-GRM155Z71A105KE01D_0402-MFG 50.546,91.948 r180 top value=1µF
C105 "GRM033C71A104KE14D" 0201 55.042,88.138 r180 top value=0.1uF
C106 "GRM033C71A104KE14D" 0201 47.498,90.424 r270 top value=0.1uF
C107 "GRM033C71A104KE14D" 0201 47.498,85.471 r0 top value=0.1uF
C108 "GRM188Z71A106KA73D" 0603 45.466,92.837 r270 top
C110 "GRM033C71A104KE14D" 0201 49.53,83.566 r0 top value=0.1uF
C111 "GRM033C71A104KE14D" 0201 47.422,88.392 r0 top value=0.1uF
C112 "GRM188Z71A106KA73D" 0603 46.99,92.837 r270 top
C113 "885012005056" FP-885012005056_0402-MFG 35.814,84.836 r270 top value=15pF
C114 "1.5pF" FP-GRM033-0_03-IPC_C 48.133,84.074 r270 top
C115 "1.5pF" FP-GRM033-0_03-IPC_C 45.593,84.582 r90 top
C116 "GRM033C71A104KE14D" 0201 55.245,91.694 r180 top value=0.1uF
C117 "885012005056" FP-885012005056_0402-MFG 35.306,84.328 r0 top value=15pF
C118 "1.2pF" FP-GRM033-0_03-IPC_C 30.734,84.582 r90 top
C119 "0.7pF" FP-GRM033-0_03-MFG 26.924,84.074 r270 top
C120 "C0603C105K3RACTU" 0603 135.001,48.26 r0 top value=1uF
C121 "C0603C102K5RACTU" 0603 135.89,45.72 r90 top value=1000pF
C122 "GRM1555C1H120JA01D" 0402 146.752,81.381 r0 top value=12pF
C123 "GRM1555C1H120JA01D" 0402 144.085,81.381 r180 top value=12pF
D1 "15408094BA400" WL-SICW_0805_L2W1.3H0.8 101.6,63.246 r90 top
D2 "15408094BA400" WL-SICW_0805_L2W1.3H0.8 97.663,59.309 r0 top
D6 "TPD1E0B04DPYR" DPY0002A 37.338,83.947 r90 top
FB1 "BLM18AG102SH1D" FP-BLM18AG102SH1D_0603-MFG 18.288,24.892 r270 top
FB2 "BLM18AG102SH1D" FP-BLM18AG102SH1D_0603-MFG 16.51,24.892 r270 top
FB3 "BLM18AG102SH1D" FP-BLM18AG102SH1D_0603-MFG 54.483,24.765 r270 top
FB4 "BLM18AG102SH1D" FP-BLM18AG102SH1D_0603-MFG 52.832,24.765 r270 top
FB5 "BLM18AG102SH1D" FP-BLM18AG102SH1D_0603-MFG 89.916,24.892 r270 top
FB6 "BLM18AG102SH1D" FP-BLM18AG102SH1D_0603-MFG 88.392,24.892 r270 top
FB7 "BLM18AG102SH1D" FP-BLM18AG102SH1D_0603-MFG 126.619,25.019 r270 top
FB8 "BLM18AG102SH1D" FP-BLM18AG102SH1D_0603-MFG 124.841,25.019 r270 top
FID1 "Fiducial" Fiducial10-20 5.08,28.194 r0 top
FID2 "Fiducial" Fiducial10-20 128.524,181.864 r0 top
FID3 "Fiducial" Fiducial10-20 151.892,25.908 r0 top
H1 "5MM HOLE" 5MM_HOLE 4.973,20 r0 top
H2 "5MM HOLE" 5MM_HOLE 4.973,170 r0 top
H3 "5MM HOLE" 5MM_HOLE 150.973,20 r0 top
H4 "5MM HOLE" 5MM_HOLE 137.973,182 r0 top
J1 "961102-6404-AR" 3M_961102-6404-AR 101.727,55.372 r270 top
J2 "Reset" 3M_961102-6404-AR 122.809,105.41 r0 top
J3 "961102-6404-AR" 3M_961102-6404-AR 97.663,55.372 r270 top
J4 "SPI Debug Header" WURTH_61300411121 18.288,48.768 r0 top
J5 "SPI Debug Header" WURTH_61300411121 54.458,48.768 r0 top locked
J6 "SPI Debug Header" WURTH_61300411121 90.17,48.768 r0 top locked
J7 "61300611121" WURTH_61300611121 95.631,90.932 r270 top
J8 "61300611121" WURTH_61300611121 90.805,91.44 r90 top
J9 "61300421121" FP-61300421121_HDR4-MFG#1 122.809,101.092 r270 top
J10 "691216610002" FP-691216610002_TERM_BLK_2-MFG 19.304,6.604 r0 top locked
J11 "691216610002" FP-691216610002_TERM_BLK_2-MFG 55.88,6.604 r0 top
J12 "691216610002" FP-691216610002_TERM_BLK_2-MFG 92.456,6.604 r0 top locked
J13 "ED120/3DS" On-Shore_ED120_3DS 37.084,5.588 r0 top locked
J14 "ED120/3DS" On-Shore_ED120_3DS 73.66,5.588 r0 top locked
J15 "ED120/3DS" On-Shore_ED120_3DS 110.236,5.588 r0 top locked
J16 "ED120/3DS" On-Shore_ED120_3DS 132.08,5.588 r0 top locked
J17 "800-10-008-10-001000" Mill-Max_800-10-008-10-001000 131.826,52.07 r0 top
J18 "61300421121" FP-61300421121_HDR4-MFG#1 122.809,109.982 r270 top
J19 "SSW-102-01-G-D" Samtec_SSW-102-01-x-D 125,15.5 r0 top locked
J20 "SSW-102-01-G-D" Samtec_SSW-102-01-x-D 32.131,15.875 r0 top
J21 "SMA-10V21-TGG" Hustsan_SMA-10V21-TGG 35.814,90.805 r0 top locked
J22 "SSW-102-01-G-D" Samtec_SSW-102-01-x-D 68.707,16.256 r0 top
J23 "SSW-102-01-G-D" Samtec_SSW-102-01-x-D 105.156,16.256 r0 top
J24 "TSW-102-07-G-D" TSW-102-07-G-D 31,65 r0 top
J25 "TSW-102-07-G-D" TSW-102-07-G-D 126.365,65 r0 top
J26 "SPI Debug Header" WURTH_61300411121 146.488,70.562 r0 top
J102 "FTSH-105-01-F-D-K" Samtec_FTSH-105-01-x-D-K 128.832,93.7 r0 top
JP1 "TSW-103-07-G-S" TSW-103-07-G-S 84.582,96.139 r270 top
JP2 "61300421121" FP-61300421121_HDR4-MFG#2 122.784,119.583 r270 top
JP3 "TSM-102-01-L-DV" Samtec_TSM-102-01-x-DV 133.045,130.555 r180 top locked
JP4 "61300311121" WURTH_61300311121 106.299,84.328 r180 top
JP5 "61300311121" WURTH_61300311121 117.983,126.238 r90 top
JP6 "61300311121" WURTH_61300311121 113.792,101.727 r270 top
JP7 "61300311121" WURTH_61300311121 104.394,106.426 r0 top
JP8 "61300311121" WURTH_61300311121 71.882,86.36 r0 top
JP9 "61300311121" WURTH_61300311121 71.882,83.058 r0 top
L1 "742792133" 1206 112.903,64.389 r90 top value="600 ohm"
L3 "10uH" FP-LQM18DN_70-IPC_B 48.768,92.583 r270 top
L4 "LQP03TN2N8B02J" "FP-LQP03TN2N8B02J_0201 (0603)-MFG" 46.863,84.328 r180 top value=2.8nH
L5 "LQP03TN2N0B02J" FP-LQP03TG_02-IPC_B 28.702,84.328 r180 top
LBL1 "THT-14-423-10" Label_650x200 83.693,164.846 r180 top
LED0 "150080SS75000" WL-SMCW_RED_0805 129.388,116.383 r90 top value=Red
LED1 "150080SS75000" WL-SMCW_RED_0805 116.078,83.439 r270 top value=Red
LED2 "LTST-C170TBKT" LTST-C170TBKT_Blue 150.47,101.93 r0 top value=Blue
LED3 "LTST-C170TBKT" LTST-C170TBKT_Blue 150.47,104.089 r0 top value=Blue
LED6 "150080SS75000" WL-SMCW_RED_0805 121.356,127.724 r270 top value=Red
LED7 "150080SS75000" WL-SMCW_RED_0805 139.075,128.333 r270 top value=Red
Logo1 "Texas Instruments" TI_Stacked_Overlay_Small 25.4,182.88 r0 top
Logo2 "CE Mark" CE_Mark_5mm 15.24,165.227 r0 top
Logo3 "FCC disclaimer" FCC_disclaimer 178.181,3.429 r90 top
Logo4 "WEEE logo" WEEE_Minimum 14.605,157.48 r0 top
LOGO5 "DANGER HIGH VOLTAGE" IEC_HighVoltage_Medium 147.828,34.163 r0 top
LOGO6 "DANGER HIGH VOLTAGE" IEC_HighVoltage_Medium 109.728,37.973 r0 top
LOGO7 "DANGER HIGH VOLTAGE" IEC_HighVoltage_Medium 38.735,38.989 r0 top
LOGO8 "DANGER HIGH VOLTAGE" IEC_HighVoltage_Medium 74.168,38.227 r0 top
MD1 "HY-23404P" FP-HY-23404P_MD16-MFG 71.247,97.663 r0 top
R1 "RC0402FR-07470RL" 0402 101.854,66.294 r90 top value=470
R2 "RC0402FR-07470RL" 0402 97.917,60.96 r180 top value=470
R3 "CRCW040247K0JNED" 0402 85.979,63.754 r0 top value=47k
R4 "CRCW04022K20JNED" 0402 120.292,84.406 r90 top value=2.2k
R5 "CRCW04020000Z0ED" 0402 121.514,84.434 r270 top value=0
R6 "CRCW06032K20JNEA" 0603 121.169,90.139 r180 bottom value=2.2k
R7 "CRCW040210K0JNED" 0402 106.045,70.358 r90 top value=10k
R8 "RC0402JR-070RL" 0402 92.466,58.892 r0 top value=0
R9 "ERJ-3GEY0R00V" 0603 91.437,57.283 r0 top value=0
R10 "CRCW040247K0JNED" 0402 87.122,96.774 r270 top value=47k
R11 "CR0402-10W-000T" FP-CR0402-10W-000T_0402-MFG 92.651,63.76 r0 top value=0uΩ
R12 "CRCW040233R0JNED" 0402 62.23,61.341 r270 top value=33
R13 "CRCW040233R0JNED" 0402 67.31,58.674 r270 top value=33
R14 "CRCW040233R0JNED" 0402 66.675,70.485 r270 top value=33
R15 "CRCW040233R0JNED" 0402 63.627,58.674 r270 top value=33
R16 "ERJ-3GEY0R00V" 0603 100.076,81.026 r0 top value=0
R17 "CRCW040233R0JNED" 0402 65.659,58.674 r270 top value=33
R18 "CRCW040233R0JNED" 0402 104.521,70.358 r90 top value=33
R19 "ERJ-3GEY0R00V" 0603 100.076,79.375 r0 top value=0
R20 "CRCW040233R0JNED" 0402 107.569,58.42 r270 top value=33
R21 "CRCW040233R0JNED" 0402 104.902,58.42 r270 top value=33
R22 "CRCW040233R0JNED" 0402 106.172,58.42 r270 top value=33
R23 "ERJ-3GEY0R00V" 0603 19.685,53.086 r90 top value=0
R24 "CRCW0603100KFKEA" 0603 99.695,70.955 r270 top value=100k
R25 "CRCW0603100KFKEA" 0603 102.87,75.184 r0 top value=100k
R26 "CRCW060333R0JNEA" 0603 22.098,53.086 r90 top value=33
R27 "CRCW060333R0JNEA" 0603 32.385,48.26 r90 top value=33
R28 "ERJ-3GEY0R00V" 0603 17.018,53.086 r90 top value=0
R29 "CRCW060333R0JNEA" 0603 13.716,44.323 r180 top value=33
R30 "CRCW060333R0JNEA" 0603 30.607,48.26 r90 top value=33
R31 "CRCW0603100KFKEA" 0603 105.791,77.724 r0 top value=100k
R32 "ERJ-3GEY0R00V" 0603 55.753,53.34 r90 top value=0
R33 "CRCW060333R0JNEA" 0603 58.166,53.34 r90 top value=33
R34 "CRCW060333R0JNEA" 0603 67.818,48.26 r90 top value=33
R35 "ERJ-3GEY0R00V" 0603 53.213,53.34 r90 top value=0
R36 "CRCW0603100KFKEA" 0603 14.351,53.086 r90 top value=100k
R37 "CRCW060333R0JNEA" 0603 49.022,44.323 r180 top locked value=33
R38 "CRCW060333R0JNEA" 0603 65.913,48.26 r90 top value=33
R39 "CRCW0603100KFKEA" 0603 50.673,53.34 r90 top value=100k
R40 "ERJ-3GEY0R00V" 0603 91.44,53.34 r90 top value=0
R41 "CRCW060333R0JNEA" 0603 94.488,51.689 r0 top value=33
R42 "CRCW0603100KFKEA" 0603 85.344,51.562 r180 top value=100k
R43 "CRCW060333R0JNEA" 0603 103.378,48.26 r90 top value=33
R44 "ERJ-3GEY0R00V" 0603 88.9,53.34 r90 top value=0
R45 "CRCW060333R0JNEA" 0603 85.09,44.323 r180 top locked value=33
R46 "CRCW060333R0JNEA" 0603 101.6,48.26 r90 top value=33
R47 "CRCW040210K0JNED" 0402 64.643,69.85 r180 top value=10k
R48 "CRCW04021M00FKED" 0402 144.374,125.136 r270 top value=1.00Meg
R49 "RC0603JR-073KL" 0603 140.903,128.341 r90 top value=3.0k
R50 "RC0402JR-070RL" 0402 137.877,120.054 r270 top value=0
R51 "RC0402JR-070RL" 0402 137.944,105.051 r270 top value=0
R52 "RC0402JR-070RL" 0402 136.7,120.054 r270 top value=0
R53 "RC0402JR-070RL" 0402 136.611,105.051 r270 top value=0
R54 "RC0603JR-075K1L" 0603 139.799,124.4 r0 top value=5.1k
R55 "RC0603JR-075K1L" 0603 139.799,122.851 r0 top value=5.1k
R56 "CRCW060349R9FKEA" 0603 25.908,23.622 r90 top value=49.9
R57 "RT0603DRD07750RL" FP-RT0603DRD07750RL_0603-MFG 25.4,21.082 r180 top
R58 "CRCW1206330KJNEA" 1206 13.843,19.558 r180 top value=330k
R59 "CRCW1206330KJNEA" 1206 18.034,16.51 r180 top value=330k
R60 "CRCW1206330KJNEA" 1206 21.082,19.05 r180 top value=330k
R61 "CRCW060349R9FKEA" 0603 27.813,21.971 r90 top value=49.9
R62 "CRCW060349R9FKEA" 0603 61.722,23.876 r90 top value=49.9
R63 "RT0603DRD07750RL" FP-RT0603DRD07750RL_0603-MFG 61.341,20.701 r180 top
R64 "CRCW1206330KJNEA" 1206 50.038,19.177 r150 top value=330k
R65 "CRCW1206330KJNEA" 1206 53.721,16.129 r180 top value=330k
R66 "CRCW1206330KJNEA" 1206 57.15,19.812 r210 top value=330k
R67 "CRCW060349R9FKEA" 0603 63.754,21.336 r90 top value=49.9
R68 "CRCW060349R9FKEA" 0603 97.663,23.749 r90 top value=49.9
R69 "RT0603DRD07750RL" FP-RT0603DRD07750RL_0603-MFG 97.79,20.955 r180 top
R70 "CRCW1206330KJNEA" 1206 86.36,19.05 r180 top value=330k
R71 "CRCW1206330KJNEA" 1206 89.789,16.637 r180 top value=330k
R72 "CRCW1206330KJNEA" 1206 93.472,19.558 r180 top value=330k
R73 "CRCW060349R9FKEA" 0603 99.695,23.749 r90 top value=49.9
R74 "RC0603JR-070RL" 0603 36.83,24.765 r90 top value=0
R75 "CRCW060349R9FKEA" 0603 36.83,28.067 r90 top value=49.9
R76 "RC0603JR-070RL" 0603 35.179,24.765 r90 top value=0
R77 "CRCW060349R9FKEA" 0603 31.242,25.654 r180 top value=49.9
R78 "RC0603JR-070RL" 0603 72.517,25.146 r90 top value=0
R79 "CRCW060349R9FKEA" 0603 72.517,28.448 r90 top value=49.9
R80 "RC0603JR-070RL" 0603 70.739,25.146 r90 top value=0
R81 "CRCW060349R9FKEA" 0603 67.093,25.856 r180 top value=49.9
R82 "RC0603JR-070RL" 0603 107.95,25.171 r90 top value=0
R83 "CRCW060349R9FKEA" 0603 107.95,28.448 r90 top value=49.9
R84 "RC0603JR-070RL" 0603 106.299,25.146 r90 top value=0
R85 "CRCW060349R9FKEA" 0603 102.616,25.908 r180 top value=49.9
R86 "ERJ-3GEY0R00V" 0603 130.429,56.896 r90 top value=0
R87 "CRCW060333R0JNEA" 0603 133.096,56.896 r90 top value=33
R88 "CRCW060333R0JNEA" 0603 138.176,56.896 r90 top value=33
R89 "ERJ-3GEY0R00V" 0603 127.762,56.896 r90 top value=0
R90 "CRCW060333R0JNEA" 0603 121.92,44.323 r180 top value=33
R91 "CRCW060333R0JNEA" 0603 135.636,56.896 r90 top value=33
R92 "RC0603JR-070RL" 0603 134.493,23.749 r90 top value=0
R93 "CRCW060349R9FKEA" 0603 134.493,27.051 r90 top value=49.9
R94 "RC0603JR-070RL" 0603 139.954,23.622 r90 top value=0
R95 "CRCW060349R9FKEA" 0603 139.954,27.051 r90 top value=49.9
R96 "RT0603DRD072KL" 0603 78.486,50.038 r270 top value=2.00k
R97 "RT0603DRD072KL" 0603 80.137,50.038 r270 top value=2.00k
R98 "RT0603DRD072KL" 0603 74.422,46.609 r180 top value=2.00k
R99 "CRCW0603100KFKEA" 0603 125.222,56.896 r90 top value=100k
R100 "RC0603JR-070RL" 0603 30.48,20.32 r180 top value=0
R101 "RC0603JR-070RL" 0603 66.167,20.447 r180 top value=0
R102 "RC0603JR-070RL" 0603 69.088,21.298 r270 top value=0
R103 "RC0603JR-070RL" 0603 101.638,20.955 r180 top value=0
R104 "RC0603JR-070RL" 0603 33.528,21.209 r270 top value=0
R105 "RC0603JR-070RL" 0603 104.394,21.755 r270 top value=0
R106 "RC0603JR-070RL" 0603 127.127,19.431 r180 top value=0
R108 "RC0603JR-073KL" 0603 121.356,124.098 r270 top value=3.0k
R109 "CRCW0402680RJNED" 0402 118.237,84.201 r90 top value=680
R110 "CRCW040252K3FKED" 0402 125.832,125.552 r270 top value=52.3k
R111 "CRCW0402680RJNED" 0402 129.388,119.421 r90 top value=680
R112 "CRCW040230K0FKED" 0402 128.321,125.552 r90 top value=30.0k
R113 "CRCW04021K00FKED" 0402 130.637,84.295 r270 top value=1.00k
R114 "CRCW04021K00FKED" 0402 129.367,84.295 r270 top value=1.00k
R115 "CRCW04021K00FKED" 0402 128.097,84.295 r270 top value=1.00k
R116 "CRCW04021K00FKED" 0402 126.827,84.295 r270 top value=1.00k
R117 "CRCW0402100RJNED" 0402 150.29,82.227 r270 top value=100
R118 "CRCW04023K30JNED" 0402 125.623,84.291 r270 top value=3.3k
R119 "RC0402FR-07470RL" 0402 147.371,101.93 r180 top value=470
R120 "RC0402FR-07470RL" 0402 147.371,104.089 r180 top value=470
R121 "CRCW040210K0JNED" 0402 137.569,81.381 r180 top value=10k
R122 "RC0201FR-7D100KL" 0201 54.229,91.821 r270 top value=100k
R123 "CR160000F" FP-CR160000F_0603-MFG 25.146,18.923 r270 top value=0
R124 "CRCW040210K0JNED" 0402 140.148,81.381 r180 top value=10k
R125 "RT0603DRD07750RL" FP-RT0603DRD07750RL_0603-MFG 61.849,18.161 r270 top
R126 "CRCW04024K87FKED" 0402 132.408,87.411 r0 top value=4.87k
R127 "CR160000F" FP-CR160000F_0603-MFG 98.298,18.034 r270 top value=0
R128 "CRCW040251R0JNED" 0402 134.991,81.39 r0 top value=51
TP1 "5000" Keystone5000 133.35,74.295 r90 top
TP4 "TESTPOINT" TP_50MIL-25MILHOLE 118.11,118.364 r90 top
TP8 "TESTPOINT" TP_50MIL-25MILHOLE 118.11,120.904 r90 top
U1 "MSPM0G3507SPM" PM0064A-MFG 88.166,74.407 r270 top
U2 "LMK1C1104PWR" PW0008A-MFG 65.329,64.389 r270 top locked
U3 "LMK1C1104PWR" PW0008A-MFG 105.791,64.389 r270 top locked
U4 "AMC131M03DFM" DFM0020A-MFG 24.282,36.957 r90 top locked
U5 "AMC131M03DFM" DFM0020A-MFG 60.096,36.957 r90 top locked
U6 "AMC131M03DFM" DFM0020A-MFG 95.656,36.957 r90 top locked
U7 "AMC131M03DFM" DFM0020A-MFG 132.08,36.957 r90 top locked
U8 "TMAG5273A2QDBVR" DBV0006A-MFG 75.692,49.784 r270 top locked
U10 "TPS3702CX33DDCR" DDC0006A_N 121.169,87.311 r90 bottom
U12 "ISOUSB111DW" DW0016B-MFG 139.802,112.663 r270 top locked
U13 "TPD4E05U06DQAR" DQA0010A 144.051,121.746 r0 top
U14 "CC2340R21E0RGER" RGE0024B-MFG 50.8,86.995 r90 top locked
U15 "RES60ADWV" DWV0008A-MFG 18.034,15.748 r0 top
U16 "RES60ADWV" DWV0008A-MFG 54.102,15.748 r0 top
U17 "RES60ADWV" DWV0008A-MFG 90.667,15.748 r0 top
U18 "MSP432E401YTPDT" PDT0128A 142.469,91.384 r270 top locked
U19 "TPD4E004DRYR" DRY0006A 127.564,109.802 r180 top
U20 "TPD4E004DRYR" DRY0006A 127.64,101.318 r270 top
U101 "TPS7A3701DRVR" DRV0006A 126.409,129.108 r90 top
USB101 "MUP-U22001" FP-MUP-U22001_CONN_USB_8MM94_8MM0-MFG 150.369,122.369 r90 top locked
Y1 "CDC6CE05000CDLE" DLE0004A-MFG 90.931,61.306 r270 top
Y2 "NX3225GA-16.000M-STD-CRG-1" NDK_NX3225GA 145.263,79.192 r90 top
Y3 "TZ3359DAAO73" FP-TZ3359DAAO73_SMT2_1MM65_1MM05-MFG 52.705,92.837 r180 top locked
Y4 "TZ3908AAAO43" FP-TZ3908AAAO43_SMT4_2MM05_1MM65-MFG 44.196,88.773 r45 top locked
ZZ1 "This Assembly Note is for PCB labels only" AssemblyNoteLabel 134.62,195.056 r0 top
ZZ2 "These assemblies are ESD sensitive, ESD precautions shall be observed." AssemblyNote 134.62,200.658 r0 top
ZZ3 "These assemblies must be clean and free from flux and all contaminants. Use of no clean flux is not acceptable." AssemblyNote 134.62,198.628 r0 top
ZZ4 "These assemblies must comply with workmanship standards IPC-A-610 Class 2, unless otherwise specified." AssemblyNote 134.62,196.79 r0 top

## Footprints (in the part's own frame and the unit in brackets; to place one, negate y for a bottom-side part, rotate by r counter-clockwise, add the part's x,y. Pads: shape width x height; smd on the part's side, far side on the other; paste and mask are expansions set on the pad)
0-MFG [mm]
  rrect22% 0.46x0.74 smd paste-1000 mask-1000: 1(-1.93,3.085)
  rrect14% 1x0.74 smd paste-1000 mask-1000: 2(-5.31,3.085) 3(-3.11,3.085)
  GND/Signal 1 region: -2.61,2.715 -12.79,2.715 -12.79,-3.455 12.79,-3.455 12.79,-2.245 -3.61,-2.245 -3.61,-0.445 -2.61,-0.445 -2.61,0.325 -1.7,1.235 -1.7,2.715 -2.16,2.715 -2.16,1.425 -2.82,0.765 -5.81,0.765 -5.81,-0.445 -4.81,-0.445 -4.81,-1.245 -10.61,-1.245 -10.61,1.425 -2.61,1.425 -2.61,2.715
3M_961102-6404-AR [mm] "Header, 2.54mm, 2x1, TH"
  rect 1.6x1.6 hole 1.1: 1(-1.27,0)
  round 1.6 hole 1.1: 2(1.27,0)
  silkscreen extent -2.52,-1.25 2.52,1.5, body extent -2.52,-1.25 2.52,1.25, height 8.5
5MM_HOLE [mm]
  round 4.7 hole 5 unplated mask+0.102: ""(0,0)
0201 [mm] "Data from Kemet datasheet CC101_COM dated 7/28/11"
  rect 0.46x0.42 smd mask+0.048: 1(-0.33,0) 2(0.33,0)
  body extent -0.31,-0.16 0.31,0.16, height 0.26
0402 [mm] "0402 from SM-752 data"
  rect 0.8x0.6 smd: 1(-0.6,0) 2(0.6,0)
  silkscreen extent -1.22,-0.52 1.22,0.52, body extent -0.55,-0.3 0.55,0.3, height 0.6
0603 [mm] "0603 from SM-752 data"
  rect 1x0.95 smd: 1(-0.8,0) 2(0.8,0)
  silkscreen extent -1.52,-0.69 1.52,0.69, body extent -0.87,-0.47 0.87,0.47, height 1
1206 [mm] "1206 from SM-752 data"
  rect 1.3x1.85 smd: 1(-1.45,0) 2(1.45,0)
  silkscreen extent -2.4,-1.21 2.4,1.21, body extent -1.7,-0.9 1.7,0.9, height 1.35
1812 [mm]
  rect 1.6x3.4 smd: 1(-2,0) 2(2,0)
  silkscreen extent -0.8,-1.6 0.8,1.6, body extent -2.4,-1.7 2.4,1.7, height 1.35
AssemblyNote [mm] "Assembly Note"
AssemblyNoteLabel [mm] "Assembly Note for PCB Labels"
CE_Mark_5mm [mm] "Minimum text height for CE Mark"
  silkscreen extent -3.5,-2.5 3.5,2.5
DBV0006A-MFG [mm]
  rrect17% 1.1x0.6 smd paste+0 mask+0: 1(-1.3,0.95) 2(-1.3,0) 3(-1.3,-0.95) 4(1.3,-0.95) 5(1.3,0) 6(1.3,0.95)
  silkscreen extent -2.52,-1.53 0.35,1.53, body extent -1.95,-1.78 1.95,1.78, height 0.25
DDC0006A_N [mm]
  rrect17% 1x0.6 smd: 1(-1.375,0.95) 2(-1.375,0) 3(-1.375,-0.95) 4(1.375,-0.95) 5(1.375,0) 6(1.375,0.95)
  silkscreen extent -1.75,-1.52 0.7,1.53, body extent -1.43,-1.48 1.43,1.49, height 0.92
DFM0020A-MFG [mm]
  rrect17% 2.1x0.6 smd paste+0 mask+0: 1(-4.85,5.715) 2(-4.85,4.445) 3(-4.85,3.175) 4(-4.85,1.905) 5(-4.85,0.635) 6(-4.85,-0.635) 7(-4.85,-1.905) 8(-4.85,-3.175) 9(-4.85,-4.445) 10(-4.85,-5.715) 11(4.85,-5.715) 12(4.85,-4.445) 13(4.85,-3.175) 14(4.85,-1.905) 15(4.85,-0.635) 16(4.85,0.635) 17(4.85,1.905) 18(4.85,3.175) 19(4.85,4.445) 20(4.85,5.715)
  silkscreen extent -6.57,-6.47 3.4,6.47, body extent -6,-6.72 6,6.72, height 0.25
DLE0004A-MFG [mm]
  rrect17% 0.6x0.7 smd paste-1000 mask+0: 1(-0.8,1.05) 2(-0.8,-1.05) 3(0.8,-1.05) 4(0.8,1.05)
  silkscreen extent -1.82,-1.65 1.3,1.65, body extent -1.4,-1.75 1.4,1.75, height 0.25
DPY0002A [mm] "X1SON-2"
  rrect57% 0.35x0.6 smd paste-0.5 mask-0.05: 1(-0.325,0) 2(0.325,0)
  rrect33% 0.3x0.5 on Top Paste: 1S(-0.35,0) 2S(0.35,0)
  silkscreen extent -0.85,-0.03 -0.8,0.02, body extent -0.5,-0.3 0.5,0.3, height 0.45
DQA0010A [mm] "SON, 10-Leads, Body 1x2.5mm, Pitch 0.5mm, TI Recommended"
  rrect50% 0.565x0.2 smd: 1(-0.417,1) 2(-0.418,0.5) 4(-0.418,-0.5) 5(-0.418,-1) 6(0.417,-1) 7(0.417,-0.5) 9(0.417,0.5) 10(0.417,1)
  rrect25% 0.565x0.4 smd: 3(-0.418,0) 8(0.417,0)
  rrect28% 0.565x0.36 on Top Paste: 3(-0.418,0) 8(0.417,0)
  silkscreen extent -0.67,-1.45 0.55,1.45, body extent -0.55,-1.3 0.55,1.3, height 0.56
DRV0006A [mm] "SON, 6-Leads, Body 2x2mm, Pitch 0.65mm, Thermal Pad 1.6x1mm, TI Recommended"
  rrect33% 0.45x0.3 smd: 1(-0.975,0.65) 2(-0.975,0) 3(-0.975,-0.65) 4(0.975,-0.65) 5(0.975,0) 6(0.975,0.65)
  rrect14% 1x0.7 on Top Paste: 7(0,0.45) 7(0,-0.45)
  rrect10% 1x1.6 smd: 7(0,0)
  silkscreen extent -1.05,-1.2 1.05,1.2, body extent -1.05,-1.05 1.05,1.05, height 0.81
DRY0006A [mm] "USON-6"
  rrect67% 0.45x0.3 smd: 1(-0.275,0.5)
  rrect67% 0.4x0.3 smd: 2(-0.3,0) 3(-0.3,-0.5) 4(0.3,-0.5) 5(0.3,0) 6(0.3,0.5)
  body extent -0.5,-0.72 0.5,0.73, height 0.58
DW0016B-MFG [mm]
  rrect17% 1.65x0.6 smd: 1(-4.875,4.445) 2(-4.875,3.175) 3(-4.875,1.905) 4(-4.875,0.635) 5(-4.875,-0.635) 6(-4.875,-1.905) 7(-4.875,-3.175) 8(-4.875,-4.445) 9(4.875,-4.445) 10(4.875,-3.175) 11(4.875,-1.905) 12(4.875,-0.635) 13(4.875,0.635) 14(4.875,1.905) 15(4.875,3.175) 16(4.875,4.445)
  silkscreen extent -6.37,-5.25 3.5,5.25, body extent -5.8,-5.5 5.8,5.5, height 0.25
DWV0008A-MFG [mm]
  rrect17% 1.8x0.6 smd paste+0 mask+0: 1(-5.45,1.905) 2(-5.45,0.635) 3(-5.45,-0.635) 4(-5.45,-1.905) 5(5.45,-1.905) 6(5.45,-0.635) 7(5.45,0.635) 8(5.45,1.905)
  silkscreen extent -7.02,-2.98 3.8,2.98, body extent -6.45,-3.22 6.45,3.22, height 0.25
FCC_disclaimer [mm]
Fiducial10-20 [mm]
  round 1 smd mask+0.5: 1(0,0)
  GND/Signal 1 keep-out circle w1.178: c0,0 r0.5
FP-61300421121_HDR4-MFG#1 [mm]
  rrect6% 1.7x1.7 hole 1.1 paste-2539.97 mask+0: 1(-1.27,1.27)
  round 1.7 hole 1.1 paste-2539.97 mask+0: 2(-1.27,-1.27) 3(1.27,1.27) 4(1.27,-1.27)
  silkscreen extent -2.69,-2.62 2.69,3.22, body extent -2.54,-2.54 2.54,2.54, height 5.54
FP-61300421121_HDR4-MFG#2 [mm]
  rrect6% 1.7x1.7 hole 1.1: 1(-1.27,1.27)
  round 1.7 hole 1.1: 2(-1.27,-1.27) 3(1.27,1.27) 4(1.27,-1.27)
  silkscreen extent -2.69,-2.62 2.69,3.22, body extent -2.54,-2.54 2.54,2.54, height 5.54
FP-691216610002_TERM_BLK_2-MFG [mm]
  rrect4% 2.3x2.3 hole 1.5 paste-2539.97 mask+0: 1(-5.38,-0.3)
  round 2.3 hole 1.5 paste-2539.97 mask+0: 2(4.78,-0.3)
  silkscreen extent -8.62,-4.95 8.02,4.95, body extent -8.12,-5.05 8.12,5.05, height 0.25
FP-885012005056_0402-MFG [mm]
  rrect20% 0.5x0.5 smd paste+0 mask+0: 1(-0.5,0) 2(0.5,0)
  silkscreen extent -0.53,-0.63 0.53,0.65, body extent -0.85,-0.38 0.85,0.38, height 0.25
FP-885012205018_0402-MFG [mm]
  rrect20% 0.5x0.5 smd paste+0 mask+0: 1(-0.5,0) 2(0.5,0)
  silkscreen extent -0.5,-0.63 0.5,0.63, body extent -0.85,-0.38 0.85,0.38, height 0.25
FP-885012205050_0402-MFG [mm]
  rrect20% 0.5x0.5 smd paste+0 mask+0: 1(-0.5,0) 2(0.5,0)
  silkscreen extent -0.53,-0.63 0.53,0.63, body extent -0.85,-0.38 0.85,0.38, height 0.25
FP-885012205064_0402-MFG [mm]
  rrect20% 0.5x0.5 smd paste+0 mask+0: 1(-0.5,0) 2(0.5,0)
  silkscreen extent -0.53,-0.63 0.53,0.63, body extent -0.85,-0.38 0.85,0.38, height 0.25
FP-BLM18AG102SH1D_0603-MFG [mm]
  rrect15% 0.65x0.7 smd paste+0 mask+0: 1(-0.675,0) 2(0.675,0)
  silkscreen extent -0.87,-0.72 0.87,0.72, body extent -1.1,-0.58 1.1,0.58, height 0.25
FP-CR0402-10W-000T_0402-MFG [mm]
  rrect17% 0.8x0.6 smd paste+0 mask+0: 1(-0.6,0) 2(0.6,0)
  silkscreen extent -0.53,-0.7 0.53,0.7, body extent -1.1,-0.4 1.1,0.4, height 0.25
FP-CR160000F_0603-MFG [mm]
  rrect15% 0.65x0.9 smd paste+0 mask+0: 1(-0.725,0) 2(0.725,0)
  silkscreen extent 0,-0.45 0,0.45, body extent -1.15,-0.55 1.15,0.55, height 0.25
FP-GRM033-0_03-IPC_C [mm]
  rect 0.354x0.263 smd paste+0 mask+0: 1(-0.254,0) 2(0.254,0)
  silkscreen extent -0.43,-0.57 0.43,0.57, body extent -0.53,-0.27 0.53,0.27, height 0.25
FP-GRM033-0_03-MFG [mm]
  rect 0.25x0.3 smd paste+0 mask+0: 1(-0.238,0) 2(0.238,0)
  silkscreen extent -0.32,-0.54 0.32,0.54, body extent -0.46,-0.27 0.46,0.27, height 0.25
FP-GRM155Z71A105KE01D_0402-MFG [mm]
  rrect25% 0.4x0.5 smd paste+0 mask+0: 1(-0.4,0) 2(0.4,0)
  silkscreen extent -0.53,-0.65 0.53,0.65, body extent -0.7,-0.38 0.7,0.38, height 0.25
FP-GRM0335C1H150GA01D_0201-IPC_B [mm]
  rrect28% 0.454x0.363 smd paste+0 mask+0: 1(-0.304,0) 2(0.304,0)
  silkscreen extent -0.53,-0.58 0.53,0.58, body extent -0.68,-0.33 0.68,0.33, height 0.25
FP-HY-23404P_MD16-MFG [mm]
  rrect13% 1x0.8 smd paste+0 mask+0: 1(-5.8,1.065) 2(-5.8,-0.205) 3(-5.8,-1.475) 4(-5.8,-2.745) 5(-5.8,-4.015) 6(-5.8,-5.285) 7(-5.8,-6.555) 8(-5.8,-7.825) 9(5.8,-7.825) 10(5.8,-6.555) 11(5.8,-5.285) 12(5.8,-4.015) 13(5.8,-2.745) 14(5.8,-1.475) 15(5.8,-0.205) 16(5.8,1.065)
  silkscreen extent -6.97,-9.06 5.9,9.06, body extent -6.4,-9.16 6.4,9.16, height 0.25
FP-LQM18DN_70-IPC_B [mm]
  rect 1.106x0.958 smd paste+0 mask+0: 1(-0.676,0) 2(0.676,0)
  silkscreen extent -1.23,-0.88 1.23,0.88, body extent -1.48,-0.73 1.48,0.73, height 0.25
FP-LQP03TG_02-IPC_B [mm]
  rect 0.454x0.363 smd paste+0 mask+0: 1(-0.304,0) 2(0.304,0)
  silkscreen extent -1.23,-0.58 0.53,0.58, body extent -0.68,-0.33 0.68,0.33, height 0.25
"FP-LQP03TN2N8B02J_0201 (0603)-MFG" [mm]
  rrect40% 0.3x0.25 smd paste+0 mask+0: 1(-0.275,0) 2(0.275,0)
  silkscreen extent -1.13,-0.54 0.32,0.53, body extent -0.53,-0.27 0.53,0.27, height 0.25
